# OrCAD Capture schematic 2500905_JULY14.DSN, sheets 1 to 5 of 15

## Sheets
1 PAGE15: size Custom
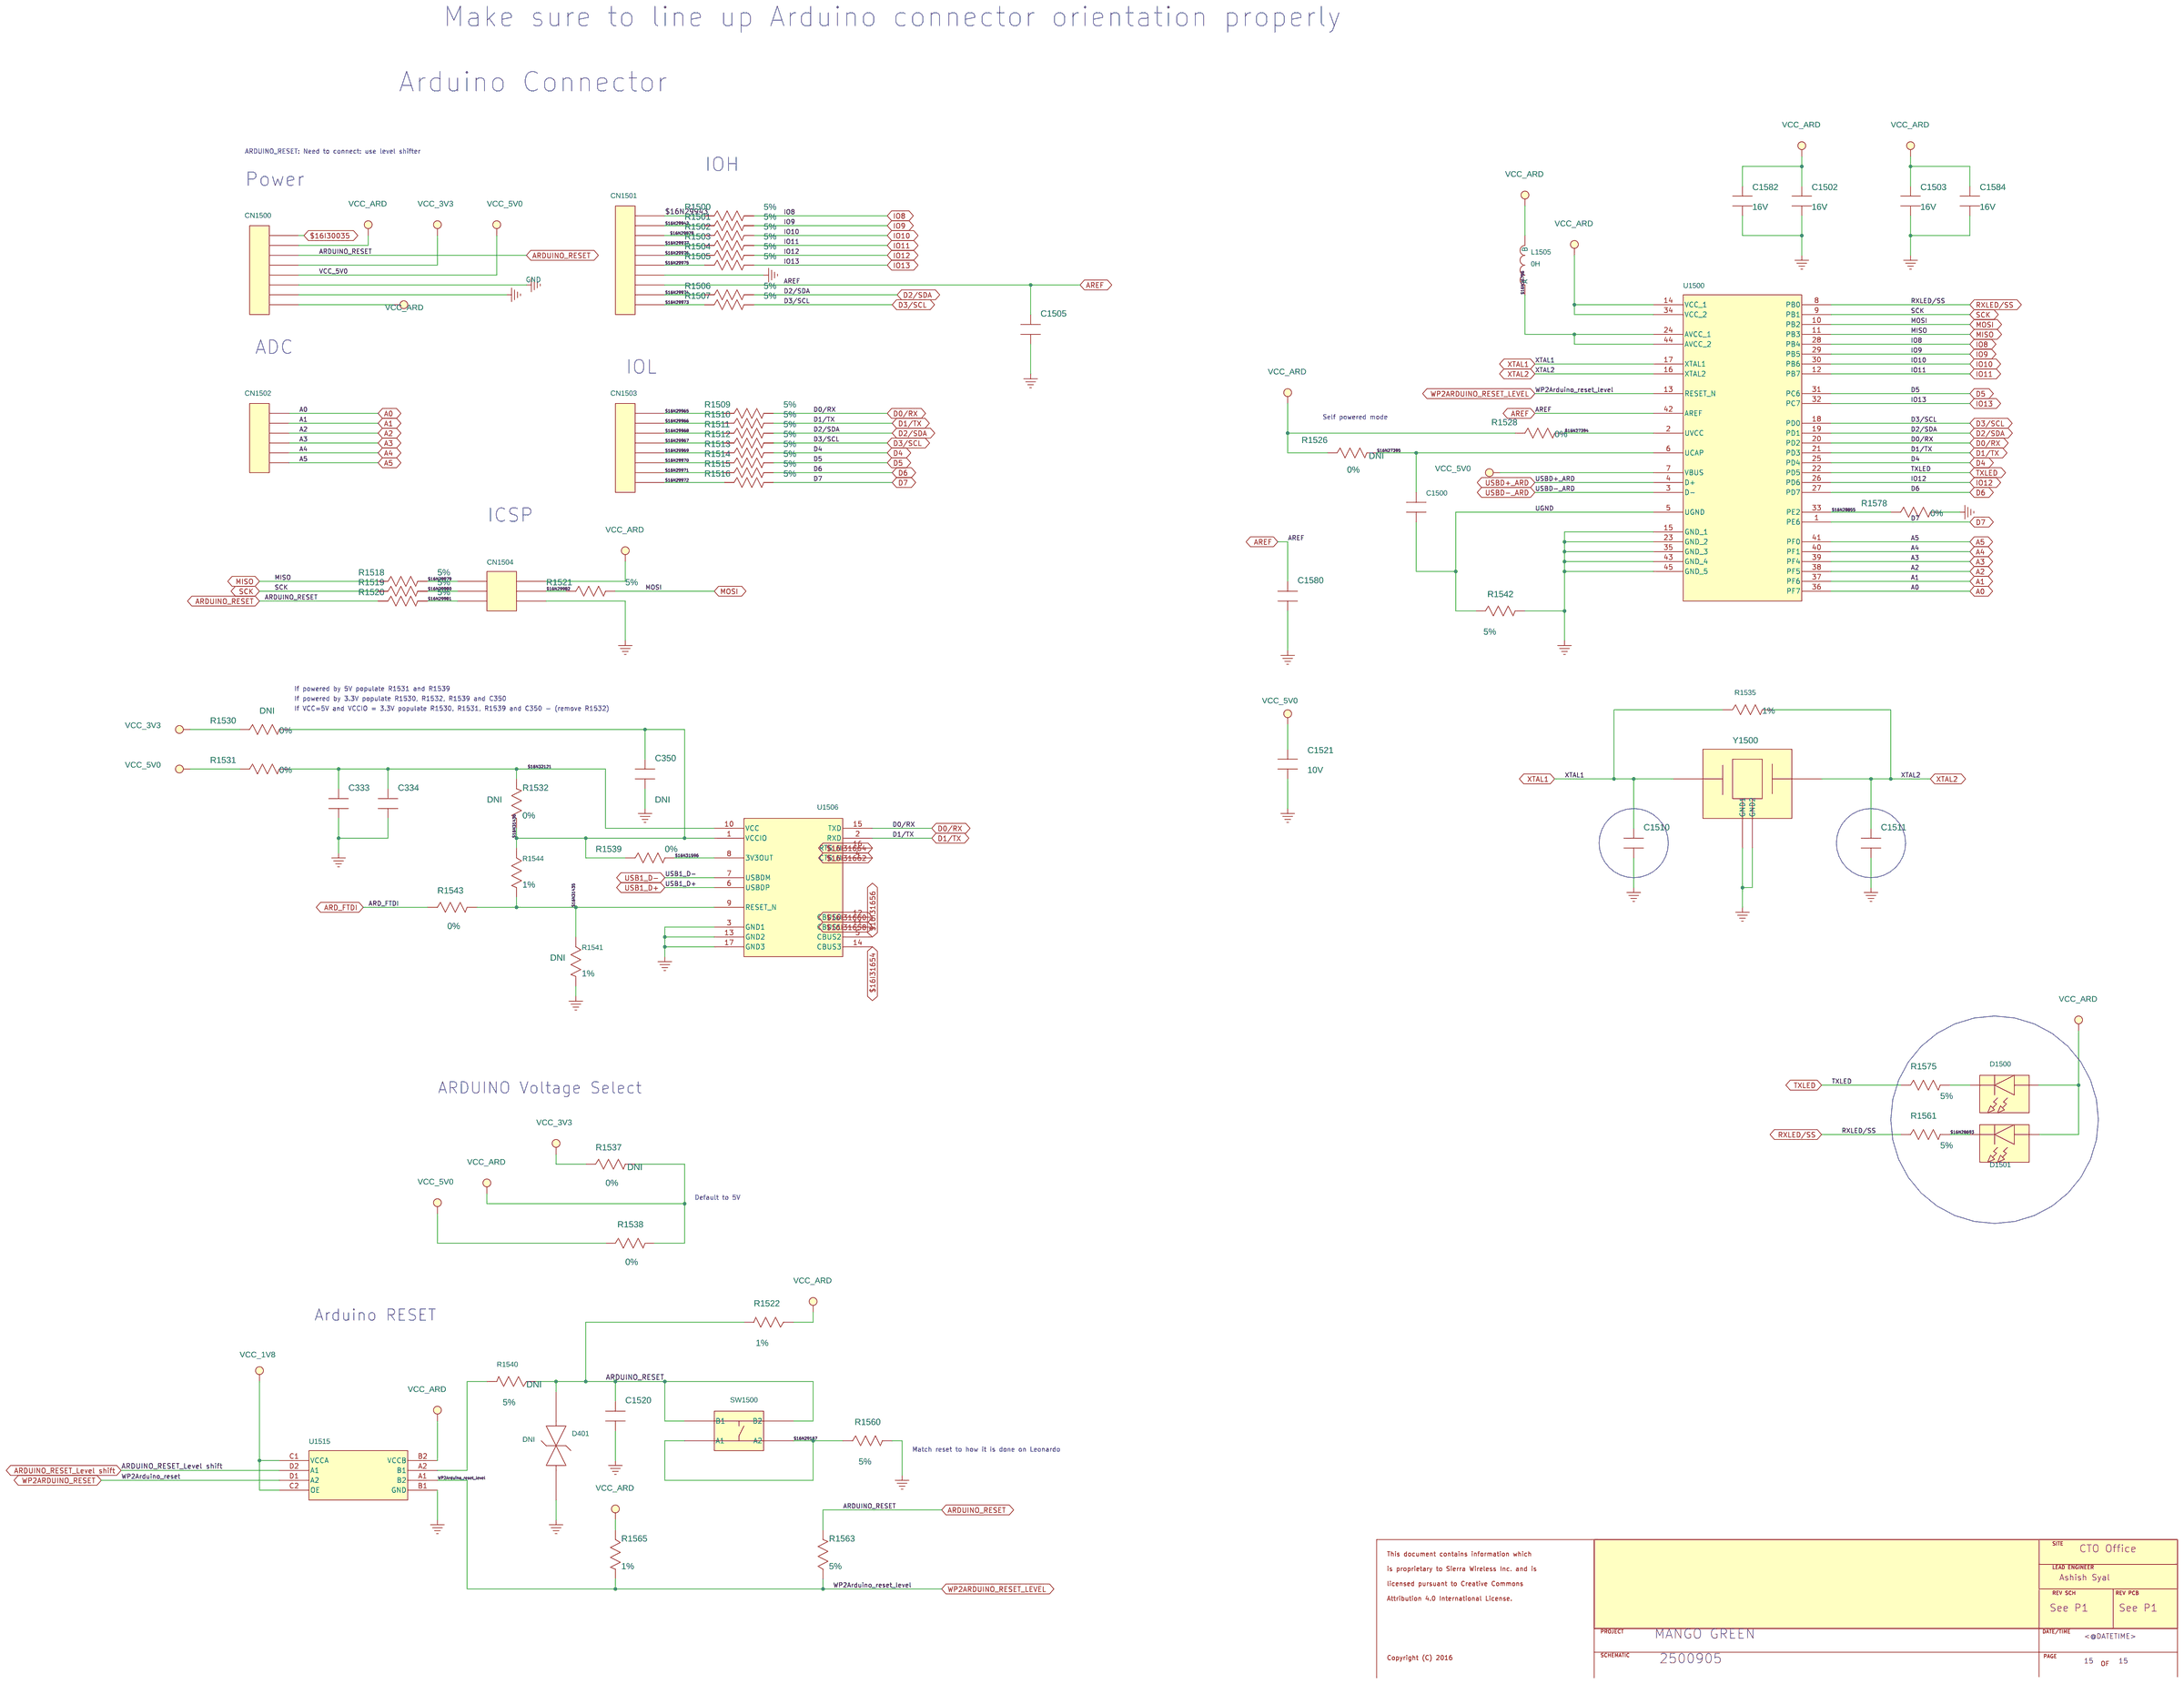
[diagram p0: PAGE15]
2 PAGE14: size Custom
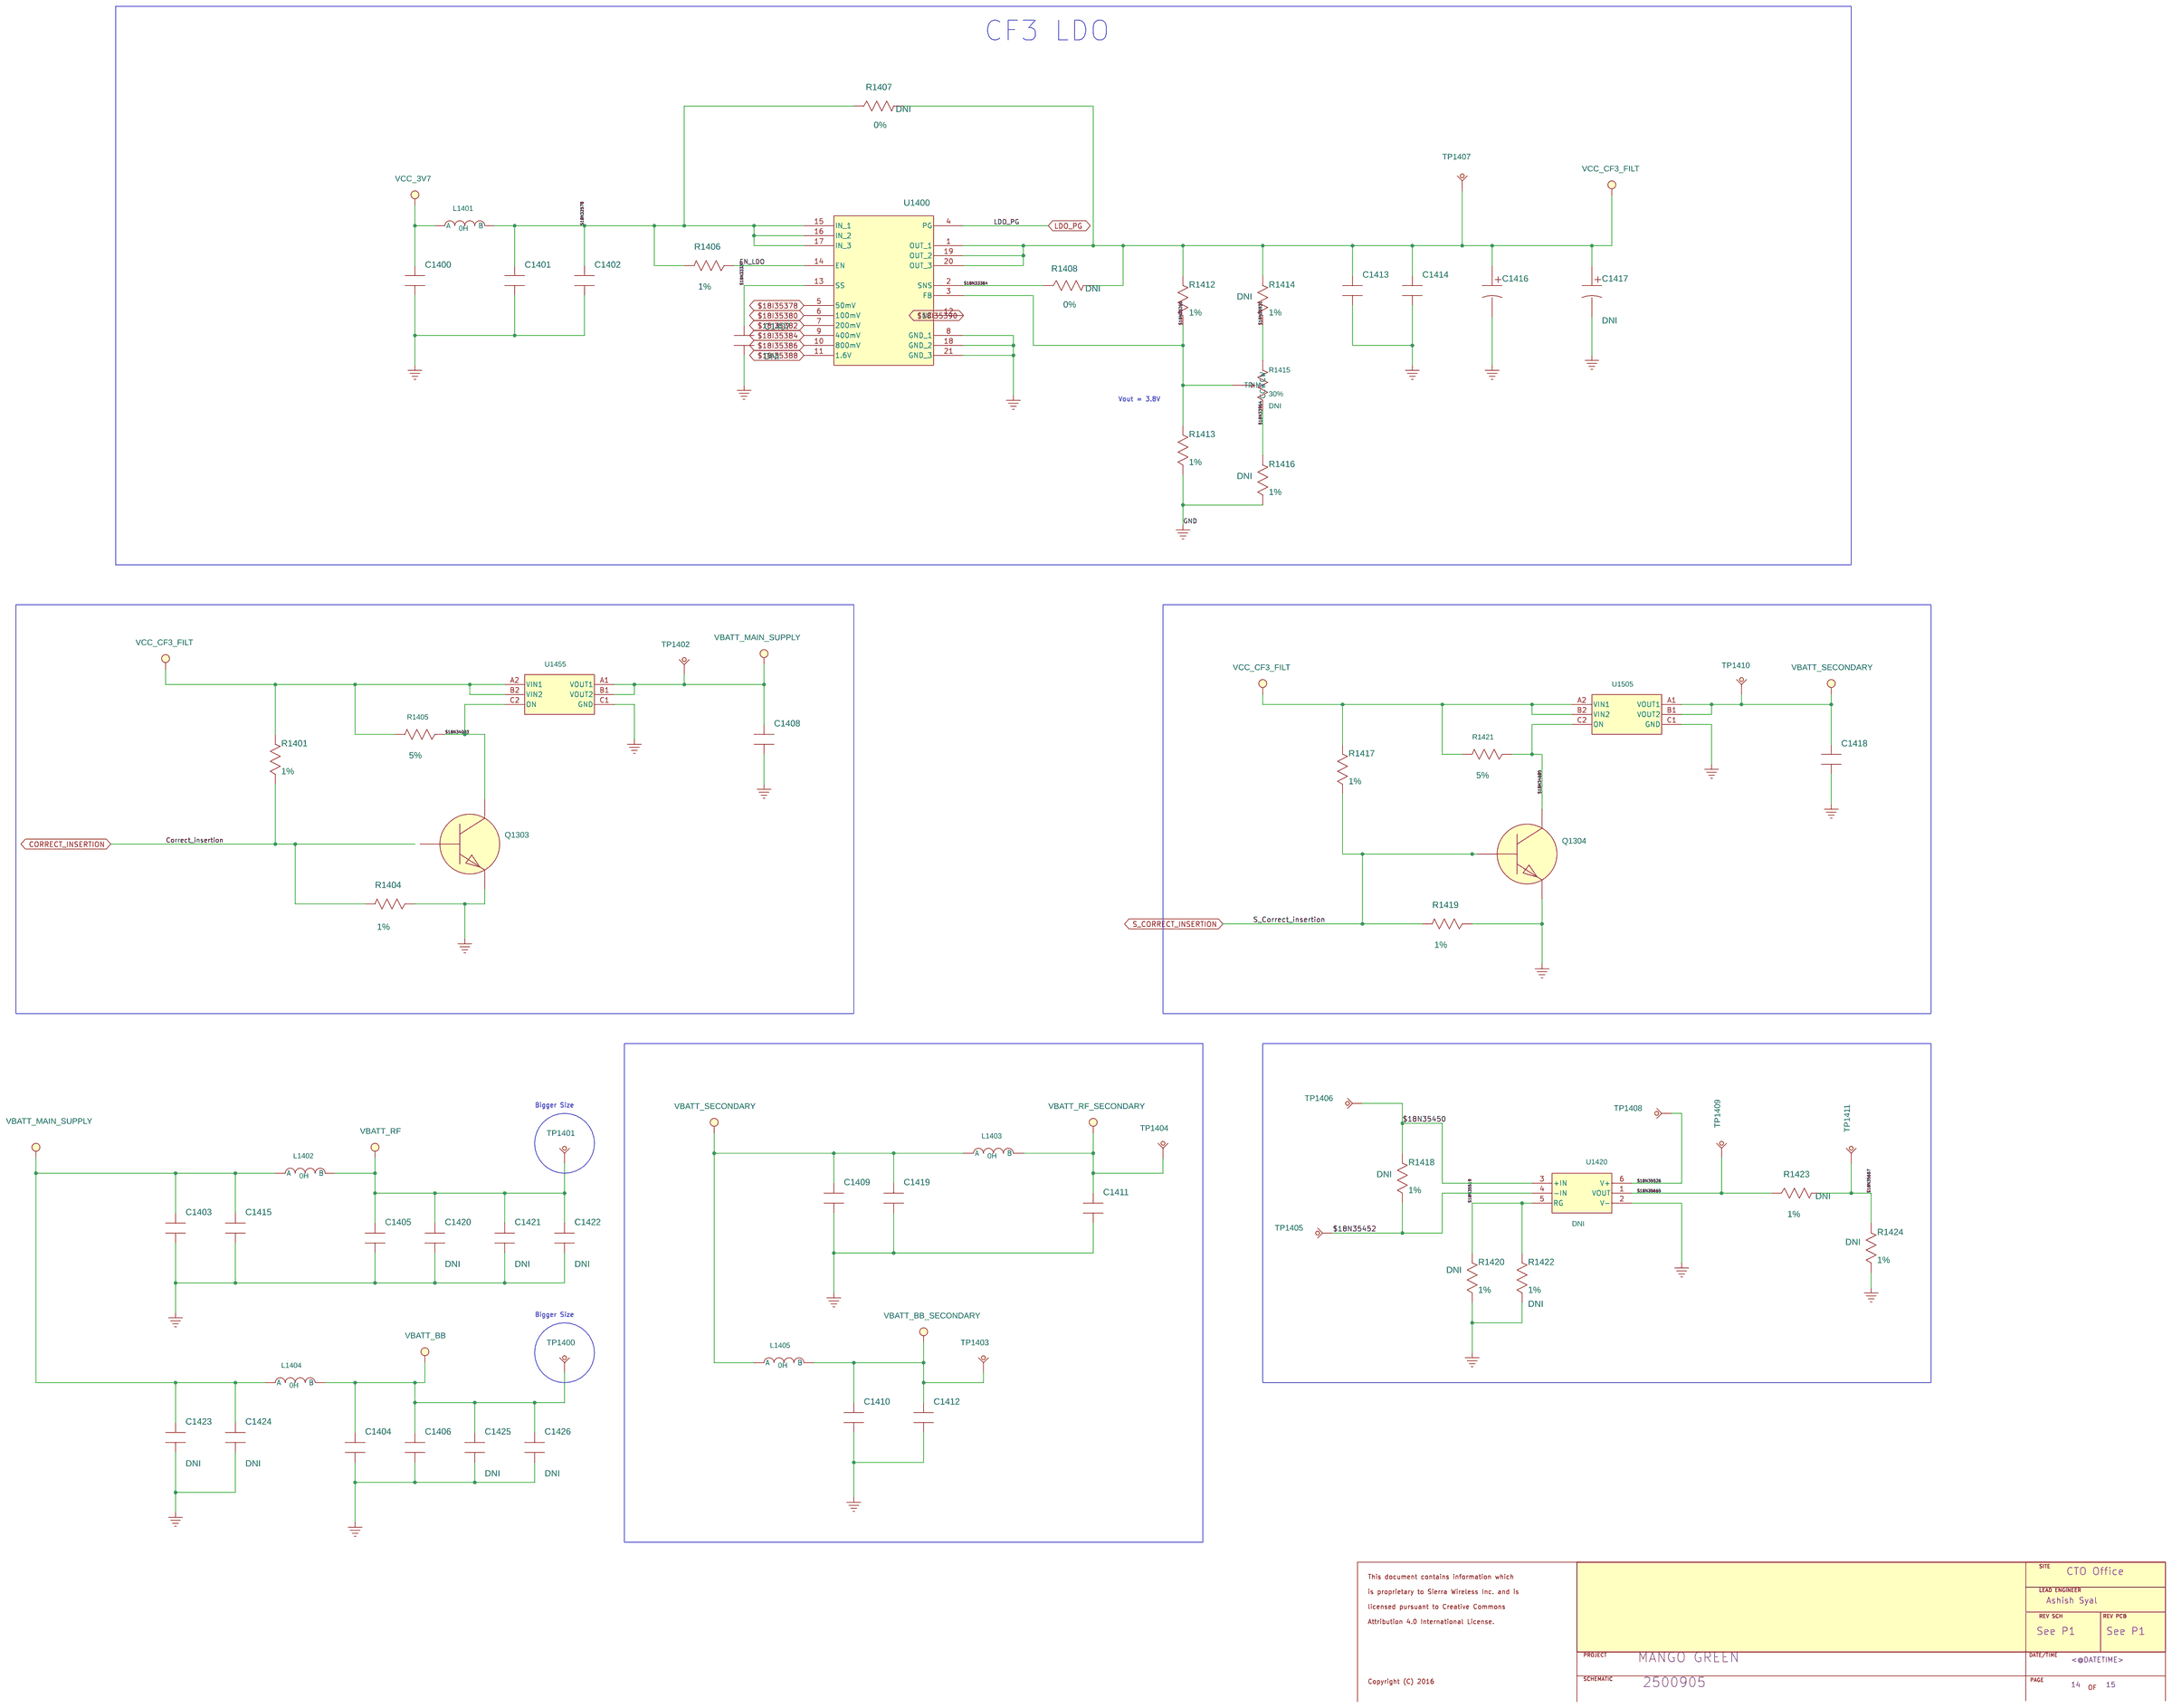
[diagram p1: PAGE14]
3 PAGE13: size Custom
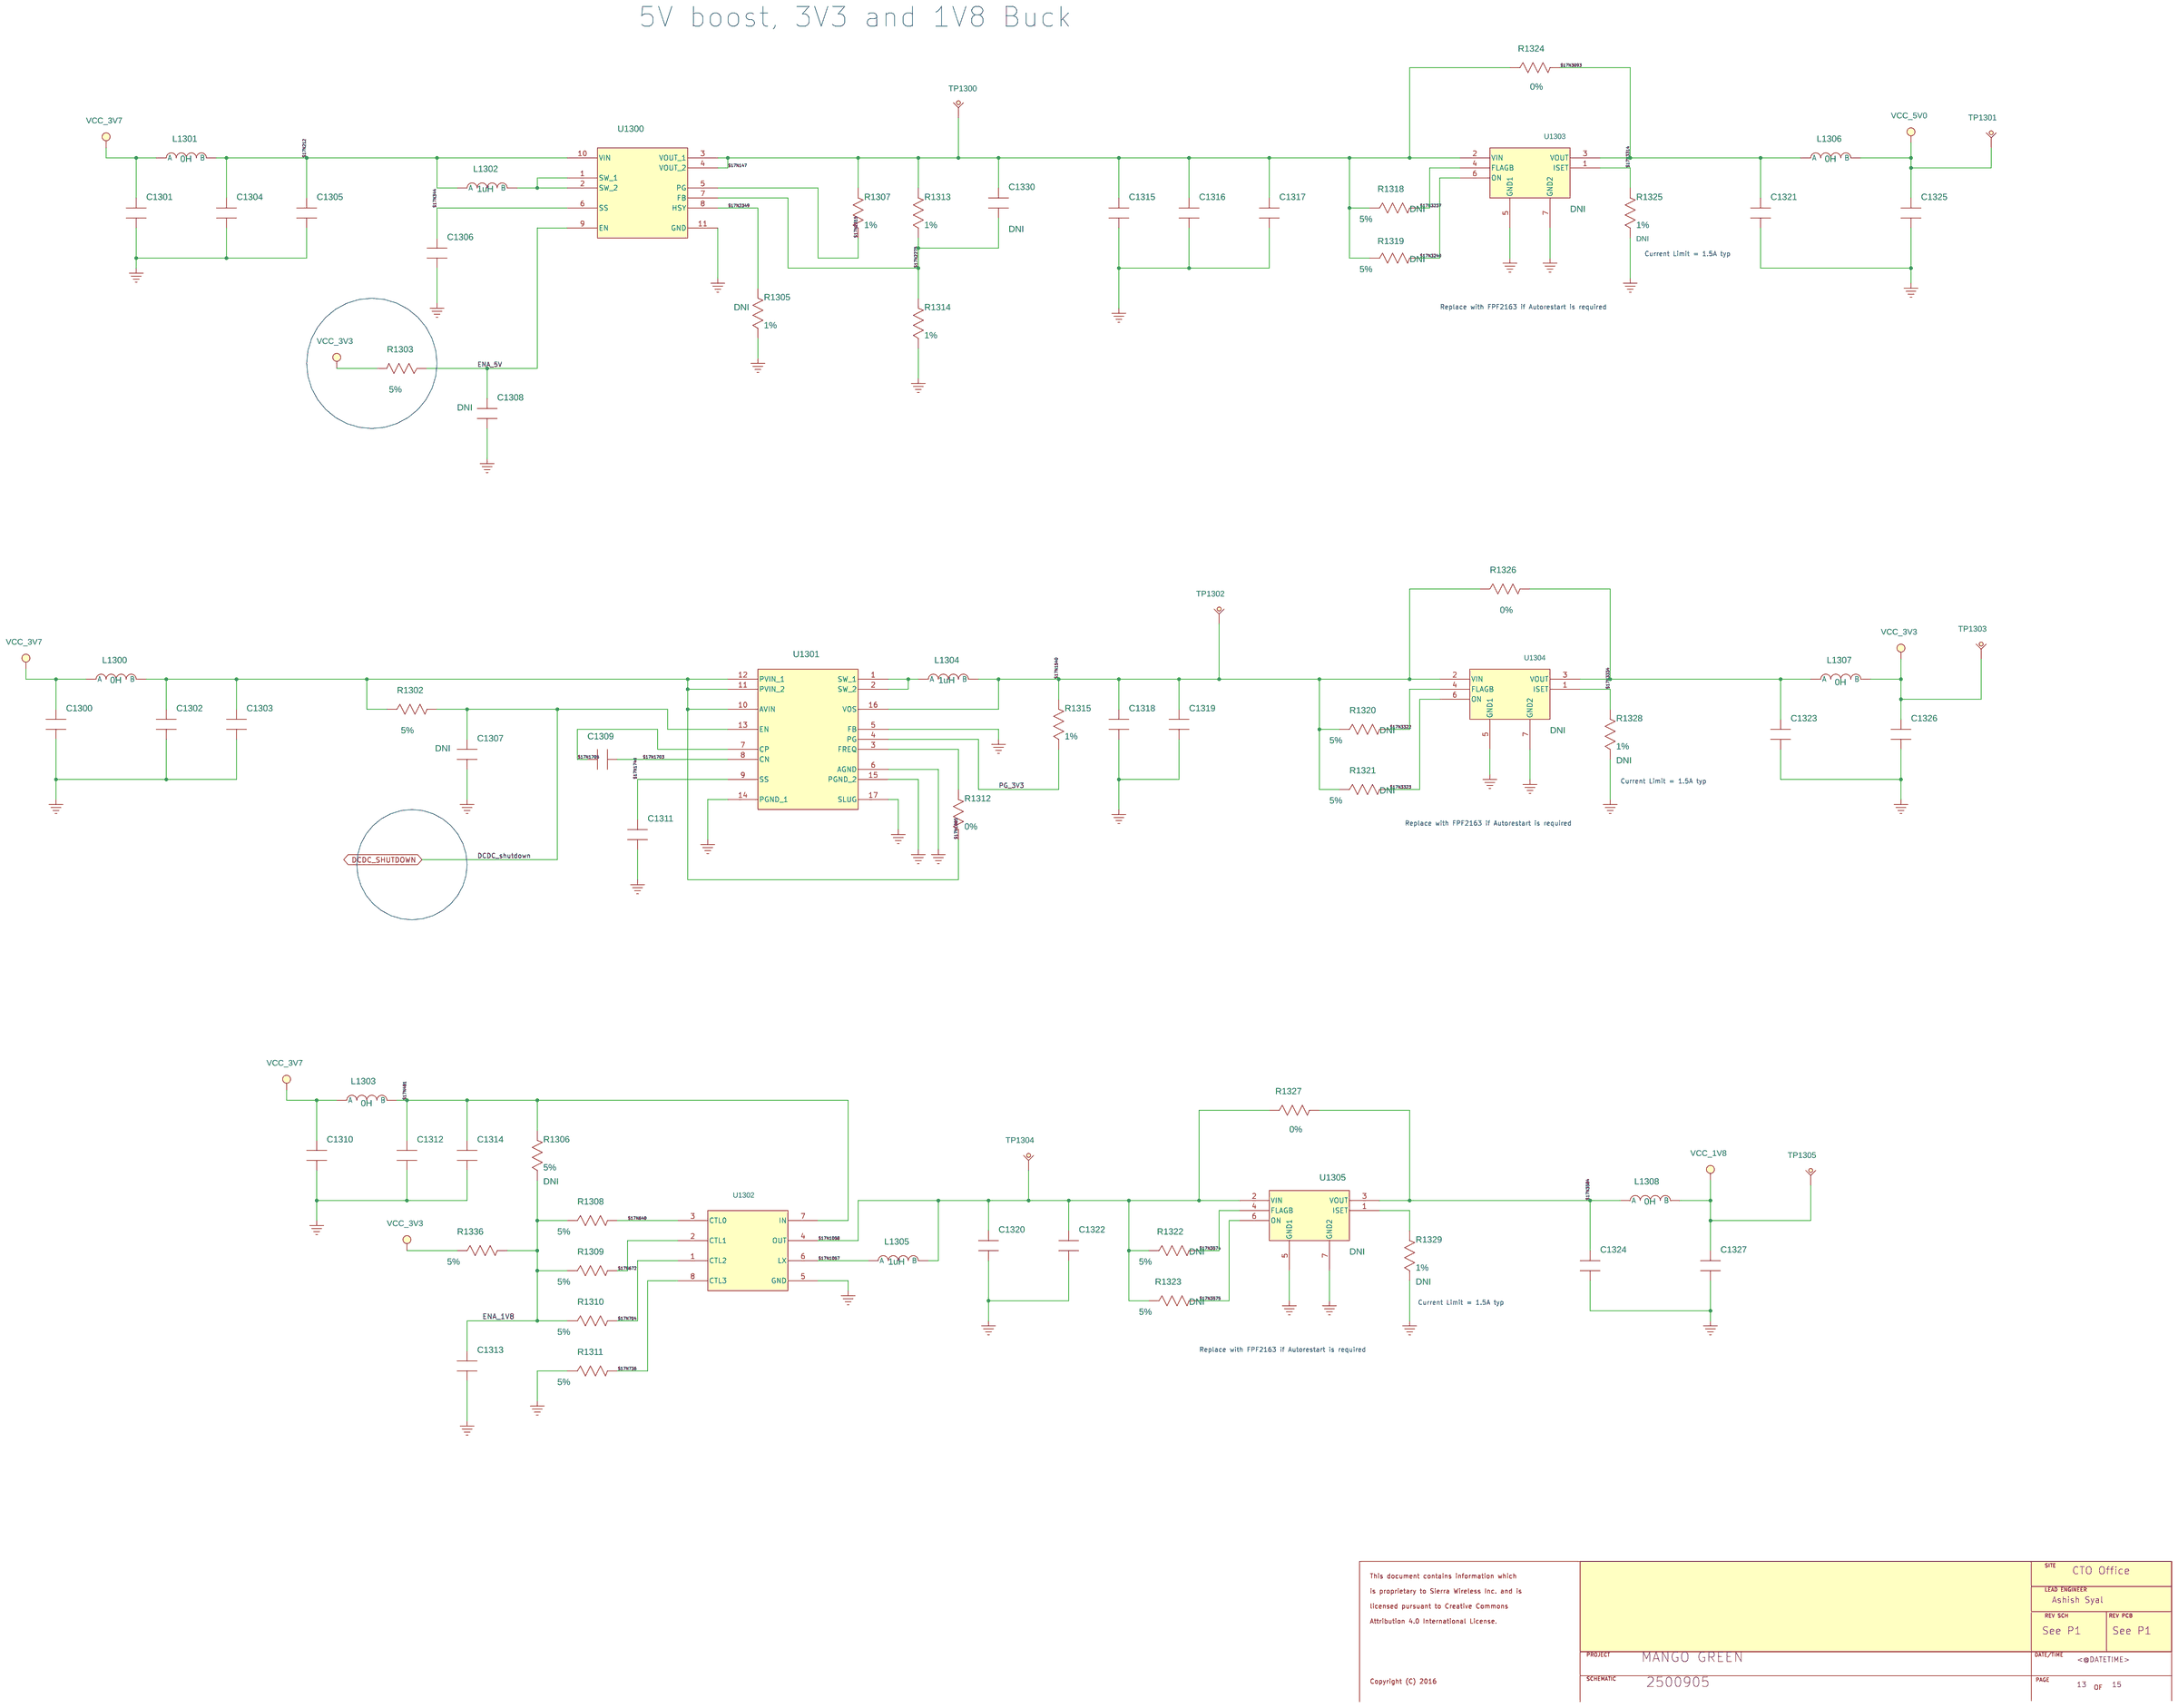
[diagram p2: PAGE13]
4 PAGE12: size Custom
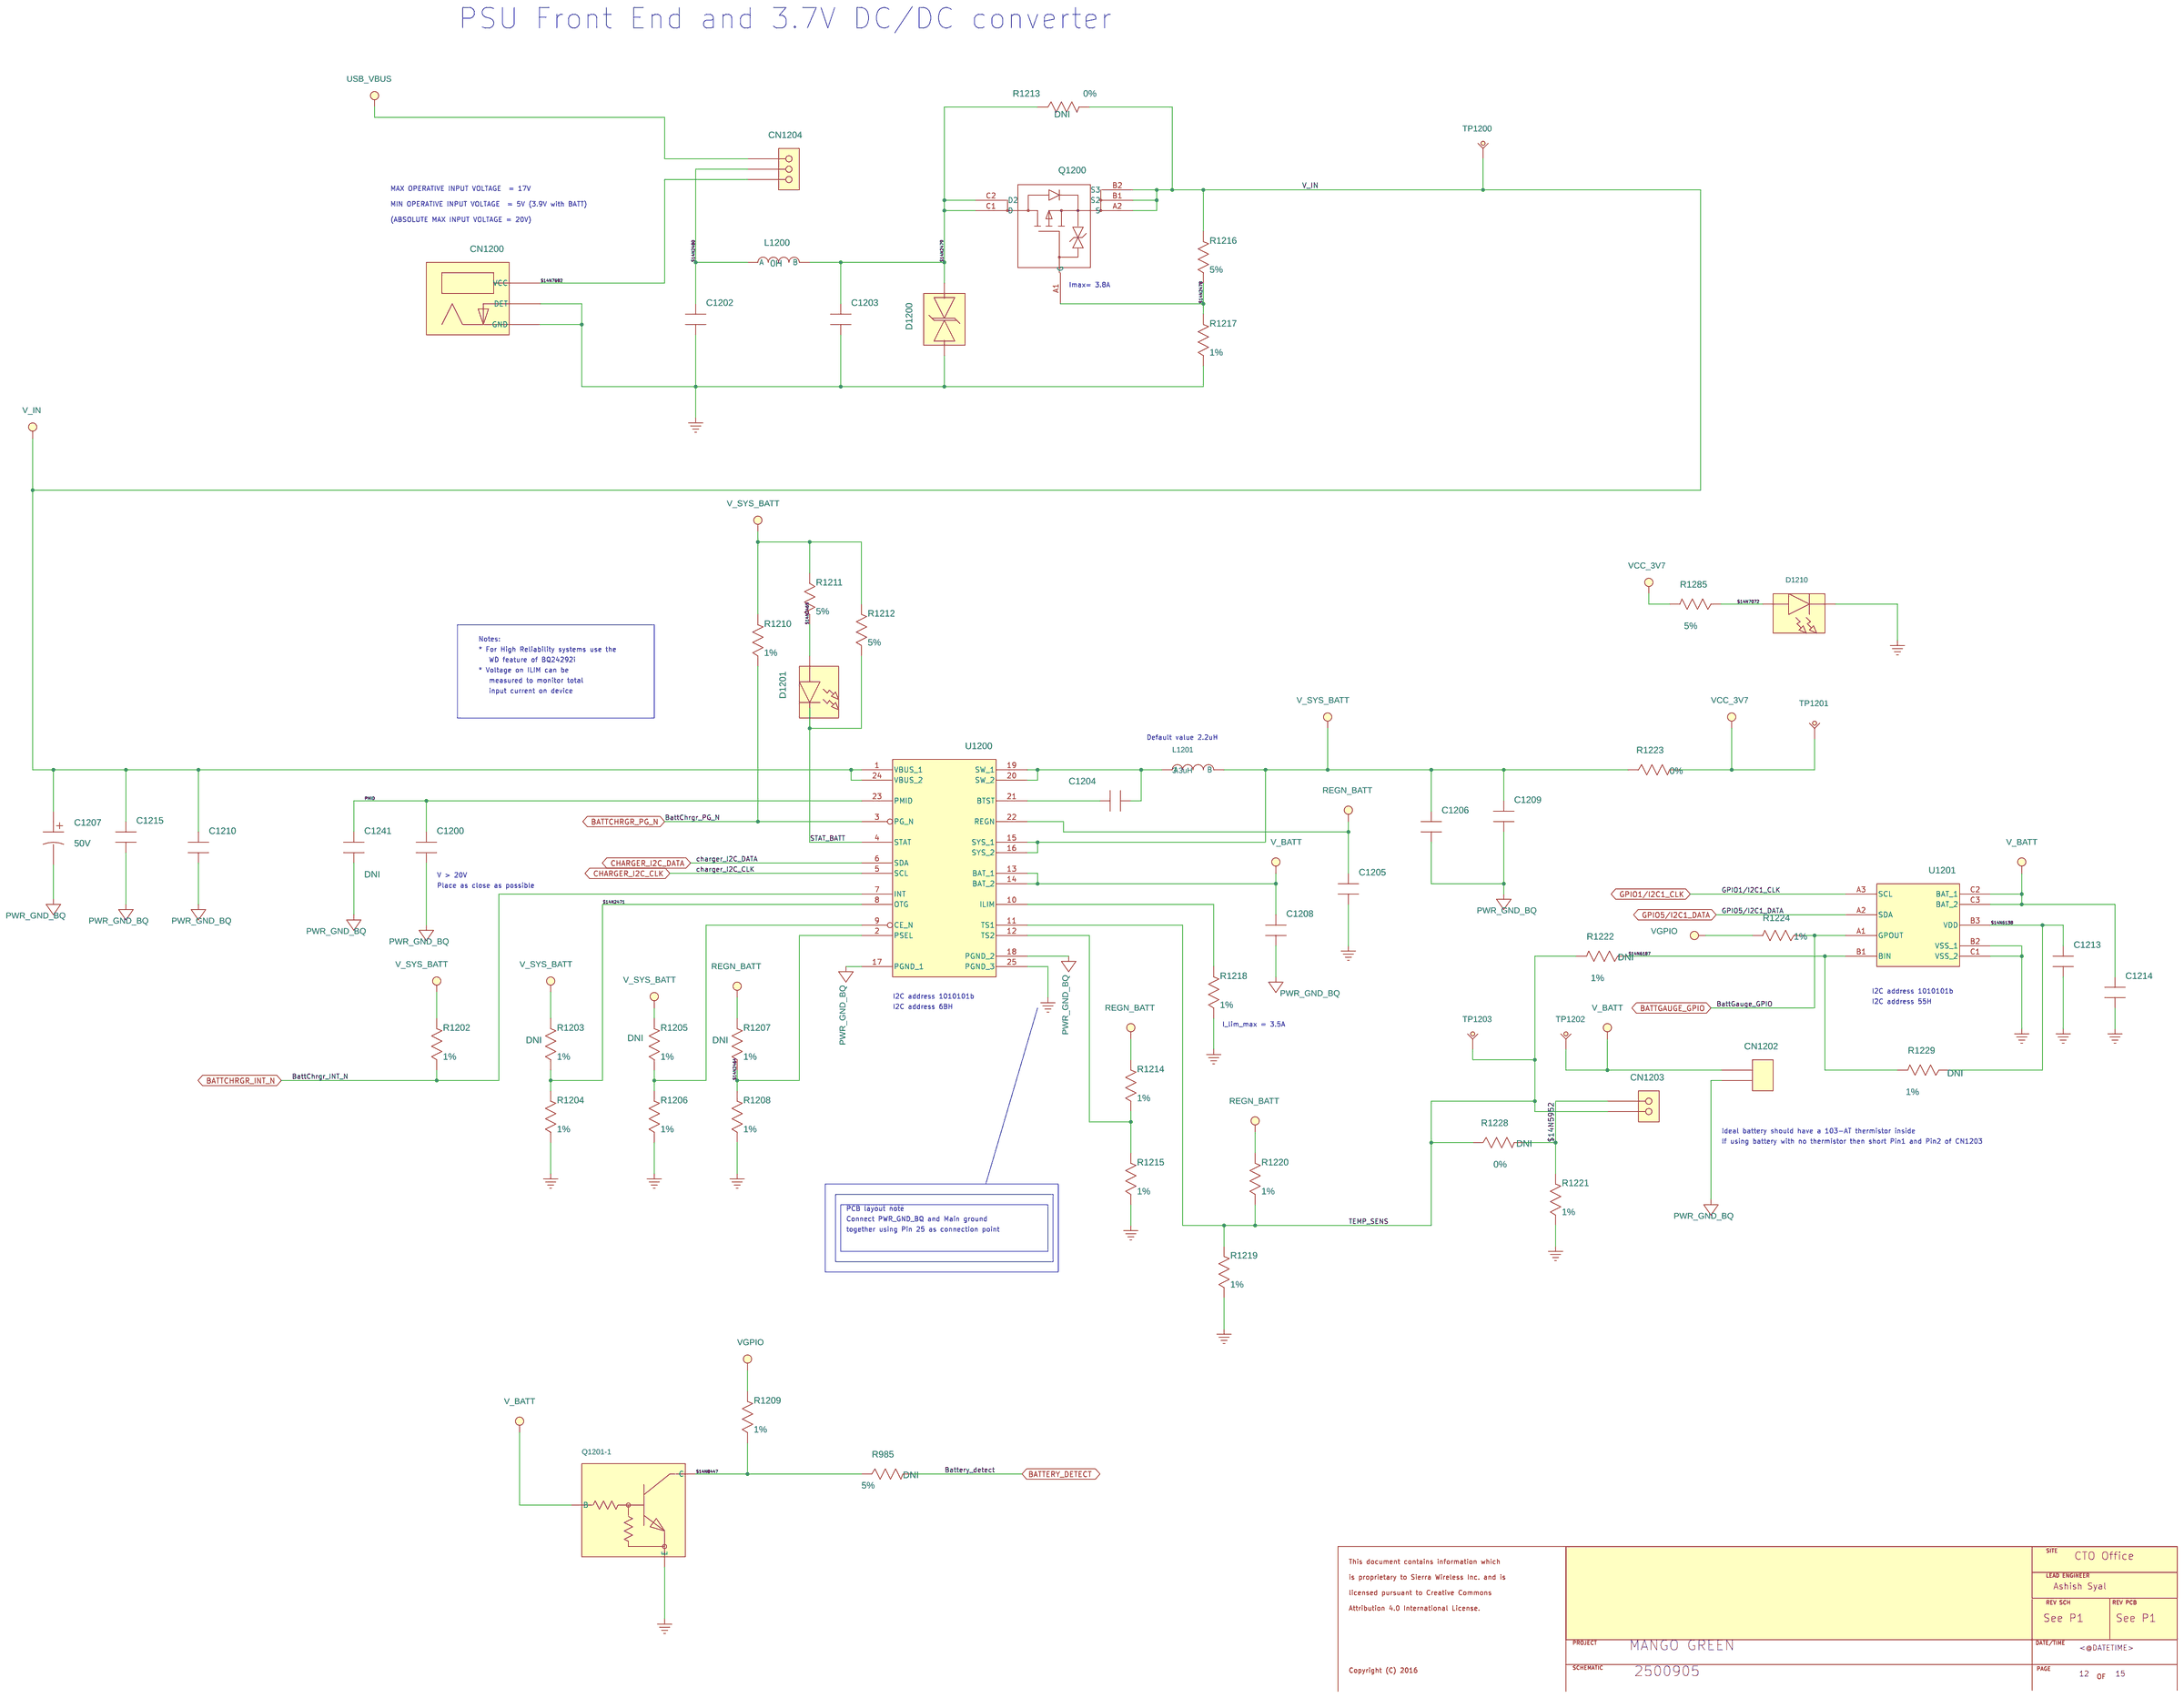
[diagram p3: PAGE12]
5 PAGE11: size Custom
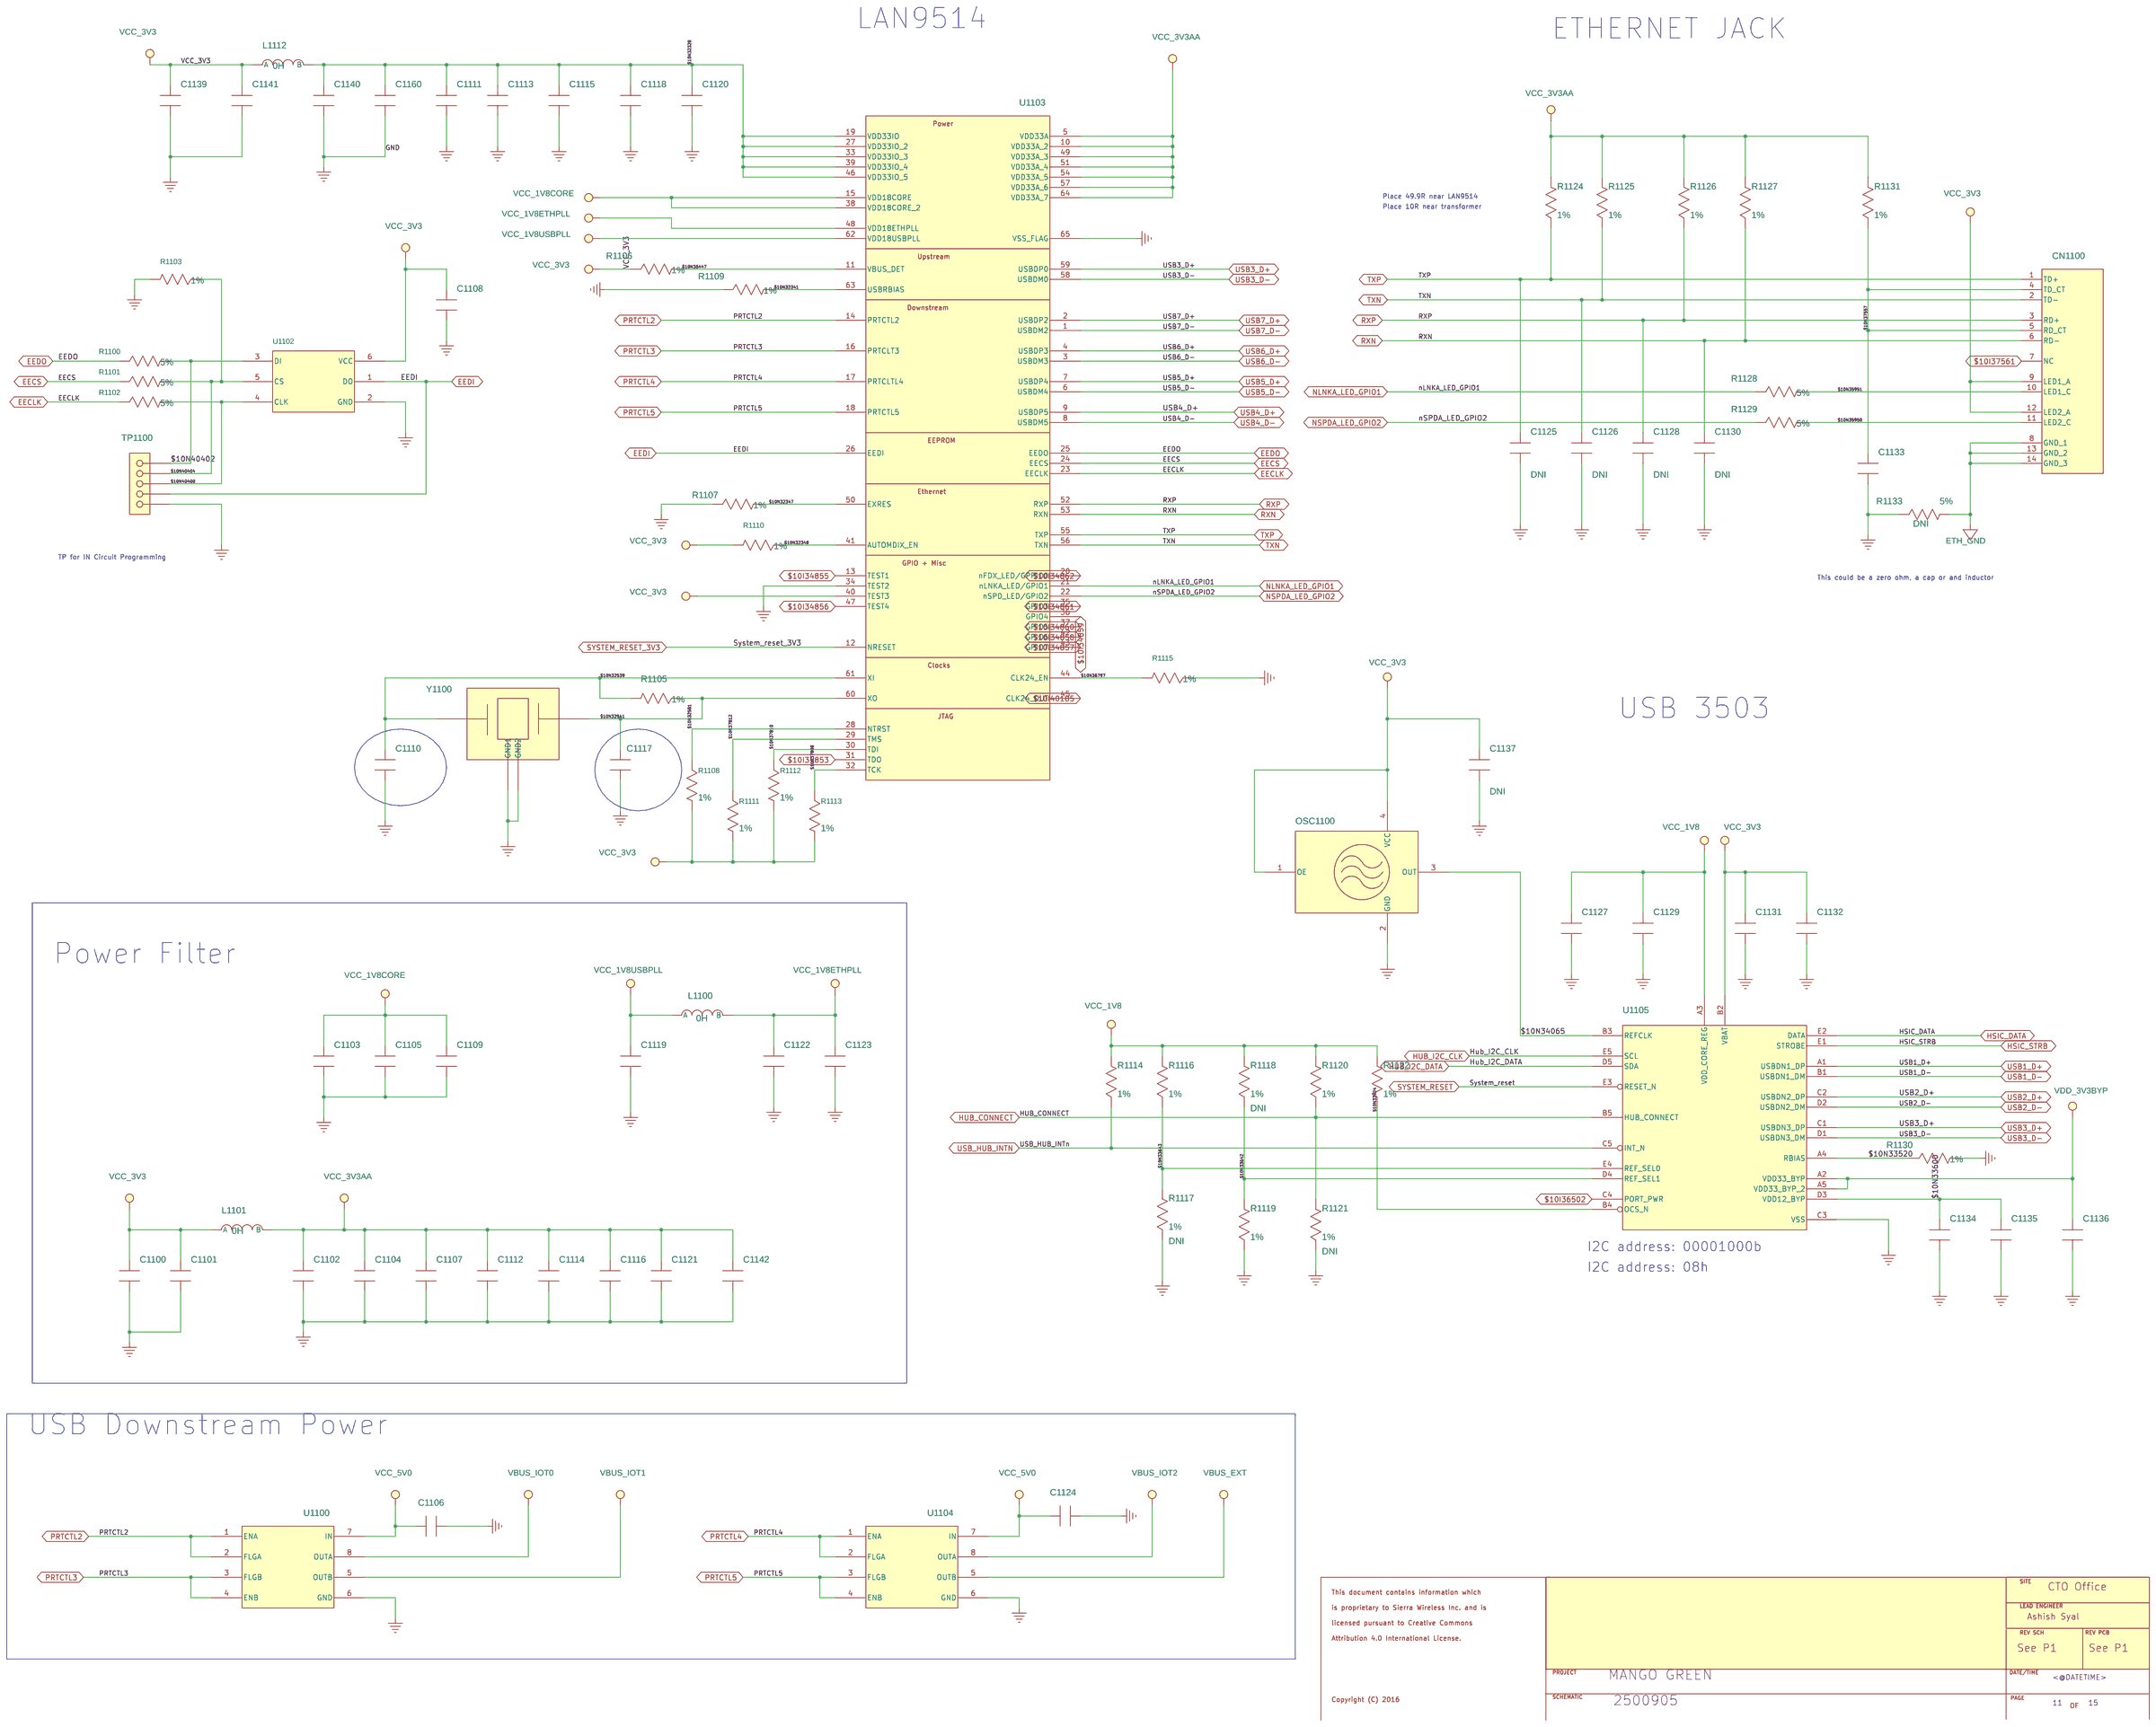
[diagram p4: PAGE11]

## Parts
sheet PAGE11
11  C_OPEN_HW  [TP]
C1100  100nF  [0402C]
C1101  100nF  [0402C]
C1102  100nF  [0402C]
C1103  4.7uF  [0402C]
C1104  100nF  [0402C]
C1105  100nF  [0402C]
C1106  1uF  [0402C]
C1107  100nF  [0402C]
C1108  100nF  [0402C]
C1109  100nF  [0402C]
C1110  22pF  [0402C]
C1111  100nF  [0402C]
C1112  100nF  [0402C]
C1113  100nF  [0402C]
C1114  100nF  [0402C]
C1115  100nF  [0402C]
C1116  100nF  [0402C]
C1117  22pF  [0402C]
C1118  100nF  [0402C]
C1119  4.7uF  [0402C]
C1120  100nF  [0402C]
C1121  4.7uF  [0402C]
C1122  100nF  [0402C]
C1123  4.7uF  [0402C]
C1124  1uF  [0402C]
C1125  15pF  [0402C]
C1126  15pF  [0402C]
C1127  100nF  [0402C]
C1128  15pF  [0402C]
C1129  4.7uF  [0402C]
C1130  15pF  [0402C]
C1131  4.7uF  [0402C]
C1132  100nF  [0402C]
C1133  22nF  [0402C]
C1134  4.7uF  [0402C]
C1135  100nF  [0402C]
C1136  4.7uF  [0402C]
C1137  100nF  [0402C]
C1139  10uF  [0603C]
C1140  10uF  [0603C]
C1141  100nF  [0402C]
C1142  100nF  [0402C]
C1160  100nF  [0402C]
CN1100  J0011D01B  [CONN_12P_1630x2160_0127CC_RJ45_2GND_PULSE]
L1100  0H  [0603L]
L1101  0H  [0603L]
L1112  0H  [0603L]
OSC1100  26MEGHz  [XTAL_4P_AP3S]
R1100  620  [0402R]
R1101  620  [0402R]
R1102  620  [0402R]
R1103  10K  [0402R]
R1105  1MEG  [0402R]
R1106  825  [0402R]
R1107  12.4K  [0402R]
R1108  10K  [0402R]
R1109  12K  [0402R]
R1110  10K  [0402R]
R1111  10K  [0402R]
R1112  10K  [0402R]
R1113  10K  [0402R]
R1114  10K  [0402R]
R1115  10K  [0402R]
R1116  10K  [0402R]
R1117  10K  [0402R]
R1118  10K  [0402R]
R1119  10K  [0402R]
R1120  10K  [0402R]
R1121  10K  [0402R]
R1122  10K  [0402R]
R1124  49.9  [0805R]
R1125  49.9  [0805R]
R1126  49.9  [0805R]
R1127  49.9  [0805R]
R1128  330  [0402R]
R1129  330  [0402R]
R1130  12K  [0402R]
R1131  10  [0402R]
R1133  20m  [1206R]
TP1100  TESTPOINT_5P_0100_RND_0127CC  [TP_5P_0100_RND_0127CC]
U1100  IC2026  [SOIC_8P_0490x0390_0127CC]
U1102  2Kbit SERIAL EEPROM  [SOT23_6P_0300x0160_0095CC]
U1103  LAN9514-JZX  [QFN_64P_0900x0900_SLUG_0730x0730_0050CC]
U1104  IC2026  [SOIC_8P_0490x0390_0127CC]
U1105  USB3503A  [BGA_25P_0200x0200_0040CC_0030PD]
Y1100  25MEGHz  [XTAL_4P_0200X0160]
sheet PAGE12
12  C_OPEN_HW  [TP]
C1200  10uF  [1206C]
C1202  220nF  [0603C]
C1203  220nF  [0603C]
C1204  47nF  [0402C]
C1205  4.7uF  [0603C]
C1206  100nF  [0402C]
C1207  22uF  [CAP_2P_0660x0660_POL]
C1208  10uF  [0603C]
C1209  47uF  [1206C]
C1210  1uF  [0603C]
C1213  470nF  [0402C]
C1214  1uF  [0402C]
C1215  220nF  [0603C]
C1241  1uF  [0603C]
CN1200  FC681465P  [CONN_3P_1450x0900_DC_PWR_JACK_CLIFF]
CN1202  B2B-PH-K-S  [CONN_2P_0590x0450_0200CC_THRU_HEADER]
CN1203  POST TERMINAL STRIP  [CONN_2P_0508x0254_VERTICAL_HEADER_SINGLE_ROW_THRU_SAMTEC_TSW]
CN1204  POST TERMINAL STRIP  [CONN_3P_0762x0254_VERTICAL_HEADER_SINGLE_ROW_THRU_SAMTEC_TSW]
D1200  SMAJ20CA  [DIO_2P_0435x0260_SMA]
D1201  LED  [0603D]
D1210  LED  [0603D]
L1200  0H  [1812L]
L1201  3.3uH  [IND_2P_0400X0400_0237CC_COILCRAFT]
Q1200  MOSFET P-CHANNEL  [BGA_6P_0100x0150_0050CC_0030PD]
Q1201  NPN  [SOT963_6P_0100x0080_0035CC]  (section -1)
R985  33  [0402R]
R1202  10K  [0402R]
R1203  10K  [0402R]
R1204  10K  [0402R]
R1205  10K  [0402R]
R1206  10K  [0402R]
R1207  10K  [0402R]
R1208  10K  [0402R]
R1209  10K  [0402R]
R1210  10K  [0402R]
R1211  300  [0402R]
R1212  47K  [0402R]
R1213  0  [0603R]
R1214  10K  [0402R]
R1215  15K  [0402R]
R1216  100K  [0603R]
R1217  10K  [0402R]
R1218  150  [0402R]
R1219  30.1K  [0402R]
R1220  5.23K  [0402R]
R1221  10K  [0402R]
R1222  10K  [0402R]
R1223  0  [0603R]
R1224  10K  [0402R]
R1228  0  [0402R]
R1229  1MEG  [0402R]
R1285  300  [0402R]
TP1200  TESTPOINT_0100_RND  [TP_0100_RND_NP]
TP1201  TESTPOINT_0100_RND  [TP_0100_RND_NP]
TP1202  TESTPOINT_0100_RND  [TP_0100_RND_NP]
TP1203  TESTPOINT_0100_RND  [TP_0100_RND_NP]
U1200  BQ24192IRGER  [QFN_24P_0400x0400_SLUG_0270x0270_0050CC]
U1201  BQ27621YZFR-G1A  [BGA_9P_0162x0158_0050CC_0030PD]
sheet PAGE13
13  C_OPEN_HW  [TP]
C1300  100nF  [0402C]
C1301  100nF  [0402C]
C1302  100nF  [0402C]
C1303  47uF  [1206C]
C1304  100nF  [0402C]
C1305  47uF  [1206C]
C1306  10nF  [0402C]
C1307  10nF  [0402C]
C1308  10nF  [0402C]
C1309  10nF  [0402C]
C1310  100nF  [0402C]
C1311  10nF  [0402C]
C1312  100nF  [0402C]
C1313  100nF  [0402C]
C1314  47uF  [1206C]
C1315  47uF  [1206C]
C1316  47uF  [1206C]
C1317  100nF  [0402C]
C1318  47uF  [1206C]
C1319  100nF  [0402C]
C1320  10uF  [0402C]
C1321  100nF  [0402C]
C1322  100nF  [0402C]
C1323  100nF  [0402C]
C1324  100nF  [0402C]
C1325  100nF  [0402C]
C1326  100nF  [0402C]
C1327  100nF  [0402C]
C1330  100nF  [0402C]
L1300  0H  [0603L]
L1301  0H  [0603L]
L1302  1uH  [IND_2P_0400x0400_0320CC_TOKO]
L1303  0H  [0603L]
L1304  1uH  [IND_2P_0400x0400_0320CC_TOKO]
L1305  1uH  [0805L]
L1306  0H  [0603L]
L1307  0H  [0603L]
L1308  0H  [0603L]
R1302  51K  [0402R]
R1303  51K  [0402R]
R1305  1MEG  [0402R]
R1306  10K  [0402R]
R1307  1MEG  [0402R]
R1308  10K  [0402R]
R1309  10K  [0402R]
R1310  10K  [0402R]
R1311  10K  [0402R]
R1312  0  [0402R]
R1313  365K  [0402R]
R1314  91K  [0402R]
R1315  499K  [0402R]
R1318  51K  [0402R]
R1319  51K  [0402R]
R1320  51K  [0402R]
R1321  51K  [0402R]
R1322  51K  [0402R]
R1323  51K  [0402R]
R1324  0  [0603R]
R1325  182  [0402R]
R1326  0  [0603R]
R1327  0  [0603R]
R1328  182  [0402R]
R1329  182  [0402R]
R1336  51K  [0402R]
TP1300  TESTPOINT_0100_RND  [TP_0100_RND_NP]
TP1301  TESTPOINT_0100_RND  [TP_0100_RND_NP]
TP1302  TESTPOINT_0100_RND  [TP_0100_RND_NP]
TP1303  TESTPOINT_0100_RND  [TP_0100_RND_NP]
TP1304  TESTPOINT_0100_RND  [TP_0100_RND_NP]
TP1305  TESTPOINT_0100_RND  [TP_0100_RND_NP]
U1300  TPS61230DRCR  [DFN_10P_0300x0300_SLUG_0240x0165_0050CC]
U1301  TPS62091RGTR  [QFN_16P_0300x0300_SLUG_0170x0170_0050CC]
U1302  SC195ULTRT  [QFN_8P_0150x0150_0040CC]
U1303  FPF2164  [DFN_6P_0200x0200_SLUG_0140x0080_0065CC]
U1304  FPF2164  [DFN_6P_0200x0200_SLUG_0140x0080_0065CC]
U1305  FPF2164  [DFN_6P_0200x0200_SLUG_0140x0080_0065CC]
sheet PAGE14
14  C_OPEN_HW  [TP]
C1400  100nF  [0402C]
C1401  100nF  [0402C]
C1402  10uF  [0603C]
C1403  47uF  [1206C]
C1404  47uF  [1206C]
C1405  100nF  [0402C]
C1406  100nF  [0402C]
C1407  47nF  [0402C]
C1408  100nF  [0402C]
C1409  47uF  [1206C]
C1410  47uF  [1206C]
C1411  100nF  [0402C]
C1412  100nF  [0402C]
C1413  47uF  [1206C]
C1414  100nF  [0402C]
C1415  100nF  [0402C]
C1416  1.5mF  [CAP_2P_0720x0630_POL_NIB]
C1417  1.5mF  [CAP_2P_0720x0630_POL_NIB]
C1418  100nF  [0402C]
C1419  100nF  [0402C]
C1420  100nF  [0402C]
C1421  100nF  [0402C]
C1422  100nF  [0402C]
C1423  100nF  [0402C]
C1424  100nF  [0402C]
C1425  100nF  [0402C]
C1426  100nF  [0402C]
L1401  0H  [0603L]
L1402  0H  [0603L]
L1403  0H  [0603L]
L1404  0H  [0603L]
L1405  0H  [0603L]
Q1303  NPN  [SOT723_3P_0120x0080_0080CC]
Q1304  NPN  [SOT723_3P_0120x0080_0080CC]
R1401  1.5K  [0402R]
R1404  220K  [0402R]
R1405  51K  [0402R]
R1406  33K  [0402R]
R1407  0  [0402R]
R1408  0  [0402R]
R1412  220K  [0402R]
R1413  33K  [0402R]
R1414  33K  [0402R]
R1415  100K  [POT_3P_0310x0360_0175CC_VERTICAL_MURATA_PVZ3A]
R1416  33K  [0402R]
R1417  1.5K  [0402R]
R1418  100m  [2010R]
R1419  220K  [0402R]
R1420  100K  [0402R]
R1421  51K  [0402R]
R1422  100K  [0402R]
R1423  10K  [0402R]
R1424  10K  [0402R]
TP1400  TESTPOINT_0200_RND  [TP_0200_RND_NP]
TP1401  TESTPOINT_0200_RND  [TP_0200_RND_NP]
TP1402  TESTPOINT_0100_RND  [TP_0100_RND_NP]
TP1403  TESTPOINT_0100_RND  [TP_0100_RND_NP]
TP1404  TESTPOINT_0100_RND  [TP_0100_RND_NP]
TP1405  TESTPOINT_0100_RND  [TP_0100_RND_NP]
TP1406  TESTPOINT_0100_RND  [TP_0100_RND_NP]
TP1407  TESTPOINT_0100_RND  [TP_0100_RND_NP]
TP1408  TESTPOINT_0100_RND  [TP_0100_RND_NP]
TP1409  TESTPOINT_0100_RND  [TP_0100_RND_NP]
TP1410  TESTPOINT_0100_RND  [TP_0100_RND_NP]
TP1411  TESTPOINT_0100_RND  [TP_0100_RND_NP]
U1400  TPS7A7300  [QFN_20P_0500x0500_SLUG_0320x0320_0065CC]
U1420  LMP8645  [SOT23_6P_0300x0160_0095CC]
U1455  TPS22964CYZPR  [BGA_6P_0100x0150_0050CC_0030PD]
U1505  TPS22964CYZPR  [BGA_6P_0100x0150_0050CC_0030PD]
sheet PAGE15
15  C_OPEN_HW  [TP]
C333  100nF  [0402C]
C334  4.7uF  [0402C]
C350  100nF  [0402C]
C1500  1uF  [0402C]
C1502  1uF  [0402C]
C1503  1uF  [0402C]
C1505  1nF  [0402C]
C1510  22pF  [0402C]
C1511  22pF  [0402C]
C1520  100nF  [0402C]
C1521  10uF  [0805C]
C1580  100nF  [0402C]
C1582  1uF  [0402C]
C1584  1uF  [0402C]
CN1500  SSW-108-01-F-S  [CONN_8P_2050x0241_0254CC_THRU]
CN1501  SSW-110-01-F-S  [CONN_10P_2550x0241_0254CC_THRU]
CN1502  SSW-106-01-F-S  [CONN_6P_1550x0241_0254CC_THRU]
CN1503  SSW-108-01-F-S  [CONN_8P_2050x0241_0254CC_THRU]
CN1504  TSW-103-07-G-D  [CONN_6P_0760x0510_HEADER_THRU_0254CC]
D401  0.05pF  [0402E]
D1500  LED  [0603D]
D1501  LED  [0603D]
L1505  0H  [0603L]
R1500  33  [0402R]
R1501  33  [0402R]
R1502  33  [0402R]
R1503  33  [0402R]
R1504  33  [0402R]
R1505  33  [0402R]
R1506  33  [0402R]
R1507  33  [0402R]
R1509  33  [0402R]
R1510  33  [0402R]
R1511  33  [0402R]
R1512  33  [0402R]
R1513  33  [0402R]
R1514  33  [0402R]
R1515  33  [0402R]
R1516  33  [0402R]
R1518  33  [0402R]
R1519  33  [0402R]
R1520  33  [0402R]
R1521  33  [0402R]
R1522  10K  [0402R]
R1526  0  [0402R]
R1528  0  [0402R]
R1530  0  [0402R]
R1531  0  [0402R]
R1532  0  [0402R]
R1535  1MEG  [0402R]
R1537  0  [0603R]
R1538  0  [0603R]
R1539  0  [0402R]
R1540  33  [0402R]
R1541  10K  [0402R]
R1542  20Meg  [1206R]
R1543  0  [0603R]
R1544  10K  [0402R]
R1560  100  [0402R]
R1561  1.5K  [0402R]
R1563  100  [0402R]
R1565  10K  [0402R]
R1575  1.5K  [0402R]
R1578  0  [0402R]
SW1500  PUSH BUTTON  [SW_4P_0600x0660_VERTICAL]
U1500  ATMEGA32U4-MU  [QFN_44P_0700x0700_SLUG_0520x0520_0050CC]
U1506  FT230XQ-R  [QFN_16P_0400x0400_SLUG_0210x0210_0065CC]
U1515  TXB0102YZPR  [BGA_8P_0095x0195_0050CC_0025PD]
Y1500  16MEGHz  [XTAL_4P_0320x0250]

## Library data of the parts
11-14 = Sierra_Title_Block_0: @DATETIME: <@DATETIME>; @Name: 2500905; @SheetTotal: 15; AUTHOR: Ashish Syal; PROJECT: MANGO GREEN; REVISION_PCB: See P1; REVISION_SCH: See P1; SITE: CTO Office
C1100-C1102 C1104 C1105 C1107-C1109 C1111-C1116 C1118 C1120 C1122 C1127 C1132 C1135 C1141 C1142 C1160 C1206 C1300-C1302 C1304 C1310 C1312 C1313 C1400 C1401 C1520 C1580 = CAP_NMC0402X7R104K16TRPF: ASSEMBLY: <ASSEMBLY>; Variant Variable Text: <Variant Variable Text>
C334 C1103 C1119 C1121 C1123 = CAP_GRM155R60J475ME87D: ASSEMBLY: <ASSEMBLY>; Variant Variable Text: <Variant Variable Text>
C1106 C1124 C1214 C1500 = CAP_GRM155R61A105KE15D: ASSEMBLY: <ASSEMBLY>; Variant Variable Text: <Variant Variable Text>
C1110 C1117 C1510 C1511 = CAP_GRM1555C1H220JA01D: ASSEMBLY: <ASSEMBLY>; Variant Variable Text: <Variant Variable Text>
C1125 C1126 C1128 C1130 = CAP_GRM1555C1H150JA01D: ASSEMBLY: DNI; Variant Variable Text: DNI
C1129 C1131 C1134 C1136 = CAP_GRM155R60J475ME47D: ASSEMBLY: <ASSEMBLY>; Variant Variable Text: <Variant Variable Text>
C1133 = CAP_GRM155R71C223KA01D: ASSEMBLY: <ASSEMBLY>; Variant Variable Text: <Variant Variable Text>
C1137 = CAP_NMC0402X7R104K16TRPF: ASSEMBLY: DNI; Variant Variable Text: DNI
C1139 C1140 = CAP_GRM188R60J106ME47D: ASSEMBLY: <ASSEMBLY>; Variant Variable Text: <Variant Variable Text>
CN1100 = CN_12P_RJ45_J0011D01B: ASSEMBLY: <ASSEMBLY>; Variant Variable Text: <Variant Variable Text>
L1100 L1101 L1112 L1300 L1303 L1307 L1308 L1505 = IND_MPZ1608S221AT
OSC1100 = TCXO_4P_ABRACON: ASSEMBLY: <ASSEMBLY>; Variant Variable Text: <Variant Variable Text>
R1100-R1102 = RES_RK73B1ETTP621J: ASSEMBLY: <ASSEMBLY>; TOLERANCE: 5%; Variant Variable Text: <Variant Variable Text>
R1103 R1108 R1110-R1116 R1119 R1120 R1122 R1202 R1204 R1206 R1208-R1210 R1214 R1217 R1221 R1522 R1544 R1565 = RES_MCR01MZPF1002: ASSEMBLY: <ASSEMBLY>; TOLERANCE: 1%; Variant Variable Text: <Variant Variable Text>
R1105 R1535 = RES_RK73H1ETTP1004F: ASSEMBLY: <ASSEMBLY>; TOLERANCE: 1%; Variant Variable Text: <Variant Variable Text>
R1106 = RES_RK73H1ETTP8250F: ASSEMBLY: <ASSEMBLY>; TOLERANCE: 1%; Variant Variable Text: <Variant Variable Text>
R1107 = RES_RK73H1ETTP1242F: ASSEMBLY: <ASSEMBLY>; TOLERANCE: 1%; Variant Variable Text: <Variant Variable Text>
R1109 R1130 = RES_RK73H1ETTP1202F: ASSEMBLY: <ASSEMBLY>; TOLERANCE: 1%; Variant Variable Text: <Variant Variable Text>
R1117 R1118 R1121 R1203 R1205 R1207 R1222 R1224 = RES_MCR01MZPF1002: ASSEMBLY: DNI; TOLERANCE: 1%; Variant Variable Text: DNI
R1124-R1127 = RES_RC0805FR-7W49R9L: ASSEMBLY: <ASSEMBLY>; TOLERANCE: 1%; Variant Variable Text: <Variant Variable Text>
R1128 R1129 = RES_MCR01MZPJ331: ASSEMBLY: <ASSEMBLY>; TOLERANCE: 5%; Variant Variable Text: <Variant Variable Text>
R1131 = RES_RK73H1ETTP10R0F: ASSEMBLY: <ASSEMBLY>; TOLERANCE: 1%; Variant Variable Text: <Variant Variable Text>
R1133 = RES_UCR18EVHJSR020: ASSEMBLY: <ASSEMBLY>; TOLERANCE: 5%; Variant Variable Text: DNI
TP1100 = TESTPOINT_5P: ASSEMBLY: <ASSEMBLY>; Variant Variable Text: <Variant Variable Text>
U1100 U1104 = IC_8P_POWER_SWITCH_MIC2026: ASSEMBLY: <ASSEMBLY>; Variant Variable Text: <Variant Variable Text>
U1102 = IC_6P_MEMORY_93AA56AT: ASSEMBLY: <ASSEMBLY>; Variant Variable Text: <Variant Variable Text>
U1103 = IC_64P_LAN9514-JZX: ASSEMBLY: <ASSEMBLY>; Variant Variable Text: <Variant Variable Text>
U1105 = IC_32P_USB_HUB_USB3503: ASSEMBLY: <ASSEMBLY>; Variant Variable Text: <Variant Variable Text>
Y1100 = XTAL_4P_XRCGB25M: ASSEMBLY: <ASSEMBLY>; Variant Variable Text: <Variant Variable Text>
C1200 = CAP_TMK316ABJ106MD-T: ASSEMBLY: <ASSEMBLY>; Variant Variable Text: <Variant Variable Text>
C1202 C1203 C1215 = CAP_GCM188R71H224MA64D: ASSEMBLY: <ASSEMBLY>; Variant Variable Text: <Variant Variable Text>
C1204 = CAP_GRM155R71A473KA01D: ASSEMBLY: <ASSEMBLY>; Variant Variable Text: <Variant Variable Text>
C1205 = CAP_GRM188R61A475KE15D: ASSEMBLY: <ASSEMBLY>; Variant Variable Text: <Variant Variable Text>
C1207 = CAP_UCD1H220MCL1GS: ASSEMBLY: <ASSEMBLY>; Variant Variable Text: <Variant Variable Text>; Voltage: 50V
C1208 C1402 = CAP_GRM188R61A106ME69D: ASSEMBLY: <ASSEMBLY>; Variant Variable Text: <Variant Variable Text>
C1209 C1303 C1305 C1314-C1316 C1318 C1403 C1404 C1409 C1410 C1413 = CAP_GRM31CR61A476ME15L: ASSEMBLY: <ASSEMBLY>; Variant Variable Text: <Variant Variable Text>
C1210 = CAP_UMK107AB7105KA-T: CAP, 1uF, 50V, 10%, X7R, CERAMIC, 0603,; ASSEMBLY: <ASSEMBLY>; Variant Variable Text: <Variant Variable Text>
C1213 = CAP_GRM155R60J474KE19D: ASSEMBLY: <ASSEMBLY>; Variant Variable Text: <Variant Variable Text>
C1241 = CAP_UMK107AB7105KA-T: ASSEMBLY: <ASSEMBLY>; Variant Variable Text: DNI
CN1200 = CN_3P_DC_PWR_JACK: ASSEMBLY: <ASSEMBLY>; Variant Variable Text: <Variant Variable Text>
CN1202 = CN_2P_SINGLE_ROW_NO_BUBBLES: ASSEMBLY: <ASSEMBLY>; Variant Variable Text: <Variant Variable Text>
CN1203 = CN_2P_SINGLE_ROW: ASSEMBLY: <ASSEMBLY>; Variant Variable Text: <Variant Variable Text>
CN1204 = CN_3P_SINGLE_ROW: ASSEMBLY: <ASSEMBLY>; Variant Variable Text: <Variant Variable Text>
D1200 = DIODE_ESD_SMAJ20CA: ASSEMBLY: <ASSEMBLY>; Variant Variable Text: <Variant Variable Text>
D1201 D1210 D1500 D1501 = LED: ASSEMBLY: <ASSEMBLY>; Variant Variable Text: <Variant Variable Text>
L1200 = IND_74279252
L1201 = IND_XAL4030-332MEB
Q1200 = P_CH_MOSFET_2D_3S: ASSEMBLY: <ASSEMBLY>; Variant Variable Text: <Variant Variable Text>
Q1201 = NPN_2RES: ASSEMBLY: <ASSEMBLY>; Variant Variable Text: <Variant Variable Text>
R985 R1540 = RES_RK73B1ETTP330J: ASSEMBLY: <ASSEMBLY>; TOLERANCE: 5%; Variant Variable Text: DNI
R1211 R1285 = RES_RK73B1ETTP301J: ASSEMBLY: <ASSEMBLY>; TOLERANCE: 5%; Variant Variable Text: <Variant Variable Text>
R1212 = RES_MCR01MZPJ473: ASSEMBLY: <ASSEMBLY>; TOLERANCE: 5%; Variant Variable Text: <Variant Variable Text>
R1213 R1223 R1324 R1326 R1327 R1537 = RES_MCR03EZPJ000: ASSEMBLY: <ASSEMBLY>; TOLERANCE: 0%; Variant Variable Text: DNI
R1215 = RES_RK73H1ETTP1502F: ASSEMBLY: <ASSEMBLY>; TOLERANCE: 1%; Variant Variable Text: <Variant Variable Text>
R1216 = RES_ERJ3GEYJ104V: ASSEMBLY: <ASSEMBLY>; TOLERANCE: 5%; Variant Variable Text: <Variant Variable Text>
R1218 = RES_RK73H1ETTP1500F: ASSEMBLY: <ASSEMBLY>; TOLERANCE: 1%; Variant Variable Text: <Variant Variable Text>
R1219 = RES_MCR01MZPF3012: ASSEMBLY: <ASSEMBLY>; TOLERANCE: 1%; Variant Variable Text: <Variant Variable Text>
R1220 = RES_RK73H1ETTP5231F: ASSEMBLY: <ASSEMBLY>; TOLERANCE: 1%; Variant Variable Text: <Variant Variable Text>
R1228 R1407 R1408 R1526 R1530 R1532 = RES_RK73Z1ETTP: ASSEMBLY: <ASSEMBLY>; TOLERANCE: 0%; Variant Variable Text: DNI
R1229 R1305 R1307 = RES_RK73H1ETTP1004F: ASSEMBLY: DNI; TOLERANCE: 1%; Variant Variable Text: <Variant Variable Text>
TP1200-TP1203 TP1300-TP1305 TP1402-TP1411 = TESTPOINT: TEST POINT, ROUND, 1mm DIAMETER; CATEGORY: Layout Feature; DXDB_LIBNAME: Layout_Feature; OWNER: Michael Sorensen; Part Height: 0.01mm; REQUESTOR: Michael Sorensen
U1200 = IC_24P_BQ24192IRGER: ASSEMBLY: <ASSEMBLY>; Variant Variable Text: <Variant Variable Text>
U1201 = IC_9P_BQ27621YZFR-G1A: ASSEMBLY: <ASSEMBLY>; Variant Variable Text: <Variant Variable Text>
C1306 C1309 C1311 = CAP_GRM155R71E103KA01D: ASSEMBLY: <ASSEMBLY>; Variant Variable Text: <Variant Variable Text>
C1307 C1308 = CAP_GRM155R71E103KA01D: ASSEMBLY: <ASSEMBLY>; Variant Variable Text: DNI
C333 C1317 C1319 C1321-C1327 C1405 C1406 C1408 C1411 C1412 C1414 C1415 C1418 C1419 = CAP_GRM155R61A104KA01D: ASSEMBLY: <ASSEMBLY>; Variant Variable Text: <Variant Variable Text>
C1320 = CAP_GRM155R60G106ME44D: ASSEMBLY: <ASSEMBLY>; Variant Variable Text: <Variant Variable Text>
C350 C1330 C1420-C1426 = CAP_GRM155R61A104KA01D: ASSEMBLY: <ASSEMBLY>; Variant Variable Text: DNI
L1301 L1306 L1401-L1405 = IND_BKP1608HS121-T
L1302 L1304 = IND_FDSD0415-H-1R0M-P3
L1305 = IND_MDT2012-CH1R0N
R1302 R1303 R1318-R1323 R1336 = RES_MCR01MZPJ513: ASSEMBLY: <ASSEMBLY>; TOLERANCE: 5%; Variant Variable Text: DNI
R1306 = RES_MCR01MZPJ103: ASSEMBLY: <ASSEMBLY>; TOLERANCE: 5%; Variant Variable Text: DNI
R1308-R1311 = RES_MCR01MZPJ103: ASSEMBLY: <ASSEMBLY>; TOLERANCE: 5%; Variant Variable Text: <Variant Variable Text>
R1312 = RES_RK73Z1ETTP: ASSEMBLY: <ASSEMBLY>; TOLERANCE: 0%
R1313 = RES_RK73H1ETTP3653F: ASSEMBLY: <ASSEMBLY>; TOLERANCE: 1%; Variant Variable Text: <Variant Variable Text>
R1314 = RES_RK73H1ETTP9102F: ASSEMBLY: <ASSEMBLY>; TOLERANCE: 1%; Variant Variable Text: <Variant Variable Text>
R1315 = RES_RK73H1ETTP4993F: ASSEMBLY: <ASSEMBLY>; TOLERANCE: 1%; Variant Variable Text: <Variant Variable Text>
R1325 R1328 R1329 = RES_RK73H1ETTP1820F: ASSEMBLY: <ASSEMBLY>; TOLERANCE: 1%; Variant Variable Text: DNI
U1300 = IC_11P_TPS61230DRCR: ASSEMBLY: <ASSEMBLY>; Variant Variable Text: <Variant Variable Text>
U1301 = IC_16P_TPS62091RGTR: ASSEMBLY: <ASSEMBLY>; Variant Variable Text: <Variant Variable Text>
U1302 = IC_8P_SD_REG_SC195ULTRT: ASSEMBLY: <ASSEMBLY>; Variant Variable Text: <Variant Variable Text>
U1303-U1305 = IC_6P_LOAD_SWITCH_FPF2164: ASSEMBLY: <ASSEMBLY>; Variant Variable Text: DNI
C1407 = CAP_GRM155R71A473KA01D: ASSEMBLY: <ASSEMBLY>; Variant Variable Text: DNI
C1416 = CAP_POL-592D158X06R3R2T20H: ASSEMBLY: <ASSEMBLY>; Variant Variable Text: <Variant Variable Text>
C1417 = CAP_POL-592D158X06R3R2T20H: ASSEMBLY: <ASSEMBLY>; Variant Variable Text: DNI
Q1303 Q1304 = NPN_1: XSTR, NPN, 50V, 150mA, SOT723-3, 1.2x0.8x0.6mm; Arena Link: https://app.bom.com/a/3L4M5P8P8RAPXOE2?v=files.associations; CATEGORY: Transistor; Commodity Class: DIS - Discretes; Created Date: 2007-06-12T14:31:59-08:00; DEVICE: 5010129; DXDB_LIBNAME: Transistor; Effective Date: 2012-03-28T13:33:02-08:00; Halogen Free: N/A; Manufacturer 1: ROHM; Manufacturer 1 PN: 2SC5658T2LQ; Manufacturer 2: ON SEMICONDUCTOR; Manufacturer 2 PN: 2SC5658M3T5G; OWNER: Brian Ng; Part Height: 0.6mm; Part Status: Production; RATING: 150mA; REQUESTOR: Chris Ivanciuc; REVISION: 2; RoHS Compliant: N/A; Temperature Range: -55 +150C; VOLTAGE: 50V
R1401 R1417 = RES_RK73H1ETTP1501F: ASSEMBLY: <ASSEMBLY>; TOLERANCE: 1%; Variant Variable Text: <Variant Variable Text>
R1404 R1412 R1419 = RES_RK73H1ETTP2203F: ASSEMBLY: <ASSEMBLY>; TOLERANCE: 1%; Variant Variable Text: <Variant Variable Text>
R1405 R1421 = RES_MCR01MZPJ513: ASSEMBLY: <ASSEMBLY>; TOLERANCE: 5%; Variant Variable Text: <Variant Variable Text>
R1406 R1413 = RES_RK73H1ETTP3302F: ASSEMBLY: <ASSEMBLY>; TOLERANCE: 1%; Variant Variable Text: <Variant Variable Text>
R1414 R1416 = RES_RK73H1ETTP3302F: ASSEMBLY: <ASSEMBLY>; TOLERANCE: 1%; Variant Variable Text: DNI
R1415 = RES_POTENTIOMETER: ASSEMBLY: <ASSEMBLY>; TOLERANCE: 30%; Variant Variable Text: DNI
R1418 = RES_PF2010FRM070R1Z: ASSEMBLY: <ASSEMBLY>; TOLERANCE: 1%; Variant Variable Text: DNI
R1420 R1422 = RES_MCR01MZPF1003: ASSEMBLY: <ASSEMBLY>; TOLERANCE: 1%; Variant Variable Text: DNI
R1423 R1424 R1541 = RES_MCR01MZPF1002: ASSEMBLY: <ASSEMBLY>; TOLERANCE: 1%; Variant Variable Text: DNI
TP1400 TP1401 = TESTPOINT: TEST POINT, ROUND, 2mm DIAMETER; CATEGORY: Layout Feature; DXDB_LIBNAME: Layout_Feature; OWNER: Michael Sorensen; Part Height: 0.01mm; REQUESTOR: Michael Sorensen
U1400 = IC_20P_LDO_TPS7A7300: ASSEMBLY: <ASSEMBLY>; Variant Variable Text: <Variant Variable Text>
U1420 = IC_6P_LMP8645: ASSEMBLY: <ASSEMBLY>; Variant Variable Text: DNI
U1455 U1505 = IC_6P_LOAD_SWITCH_FPF1038: ASSEMBLY: <ASSEMBLY>; Variant Variable Text: <Variant Variable Text>
15 = Sierra_Title_Block_0: @DATETIME: <@DATETIME>; @Name: 2500905; AUTHOR: Ashish Syal; PROJECT: MANGO GREEN; REVISION_PCB: See P1; REVISION_SCH: See P1; SITE: CTO Office
C1502 C1503 C1582 C1584 = CAP_EMK105BJ105KV-F: ASSEMBLY: <ASSEMBLY>; Variant Variable Text: <Variant Variable Text>; Voltage: 16V
C1505 = CAP_GRM155R71H102KA01D: ASSEMBLY: <ASSEMBLY>; Variant Variable Text: <Variant Variable Text>
C1521 = CAP_LMK212C106MG: ASSEMBLY: <ASSEMBLY>; Variant Variable Text: <Variant Variable Text>; Voltage: 10V
CN1500 CN1503 = CN_8P_SINGLE_ROW_NO_BUBBLES: ASSEMBLY: <ASSEMBLY>; Variant Variable Text: <Variant Variable Text>
CN1501 = CN_10P_SINGLE_ROW_NO_BUBBLES: ASSEMBLY: <ASSEMBLY>; Variant Variable Text: <Variant Variable Text>
CN1502 = CN_6P_SINGLE_ROW_NO_BUBBLES: ASSEMBLY: <ASSEMBLY>; Variant Variable Text: <Variant Variable Text>
CN1504 = CN_6P_DUAL_ROW_Z_NO_BUBBLES: ASSEMBLY: <ASSEMBLY>; Variant Variable Text: <Variant Variable Text>
D401 = DIODE_ESD_SUPPRESSOR: ASSEMBLY: <ASSEMBLY>; Variant Variable Text: DNI
R1500-R1507 R1509-R1516 R1518-R1521 = RES_RK73B1ETTP330J: ASSEMBLY: <ASSEMBLY>; TOLERANCE: 5%; Variant Variable Text: <Variant Variable Text>
R1528 R1531 R1539 R1578 = RES_RK73Z1ETTP: ASSEMBLY: <ASSEMBLY>; TOLERANCE: 0%; Variant Variable Text: <Variant Variable Text>
R1538 = RES_MCR03EZPJ000: ASSEMBLY: <ASSEMBLY>; TOLERANCE: 0%; Variant Variable Text: <Variant Varibale Text>
R1542 = RES_UCR18EVHJSR020: ASSEMBLY: <ASSEMBLY>; TOLERANCE: 5%; Variant Variable Text: <Variant Variable Text>
R1543 = RES_MCR03EZPJ000: ASSEMBLY: <ASSEMBLY>; TOLERANCE: 0%; Variant Variable Text: <Variant Variable Text>
R1560 R1563 = RES_RK73B1ETTP101J: ASSEMBLY: <ASSEMBLY>; TOLERANCE: 5%; Variant Variable Text: <Variant Variable Text>
R1561 R1575 = RES_RK73B1ETTP152J: ASSEMBLY: <ASSEMBLY>; TOLERANCE: 5%; Variant Variable Text: <Variant Variable Text>
SW1500 = SW_4P_B3S-1002: ASSEMBLY: <ASSEMBLY>; Variant Variable Text: <Variant Variable Text>
U1500 = IC_44P_MC_ATMEGA32U4-MU: ASSEMBLY: <ASSEMBLY>; Variant Variable Text: <Variant Variable Text>
U1506 = IC_16P_USB_UART_FT230XQ-R: ASSEMBLY: <ASSEMBLY>; Variant Variable Text: <Variant Variable Text>
U1515 = IC_8P_TI_TXB0102YZPR: ASSEMBLY: <ASSEMBLY>; Variant Variable Text: <Variant Variable Text>
Y1500 = XTAL_4P_KX-7T-16MHZ: ASSEMBLY: <ASSEMBLY>; Variant Variable Text: <Variant Variable Text>

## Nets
GND: C333.1(A) C334.1(A) C350.1(A) C1100.1(A) C1101.1(A) C1102.1(A) C1103.1(A) C1104.1(A) C1105.1(A) C1106.2(B) C1107.1(A) C1108.1(A) C1109.1(A) C1110.1(A) C1111.1(A) C1112.1(A) C1113.1(A) C1114.1(A) C1115.1(A) C1116.1(A) C1117.1(A) C1118.1(A) C1119.1(A) C1120.1(A) C1121.1(A) C1122.1(A) C1123.1(A) C1124.2(B) C1125.1(A) C1126.1(A) C1127.1(A) C1128.1(A) C1129.1(A) C1130.1(A) C1131.1(A) C1132.1(A) C1133.1(A) C1134.1(A) C1135.1(A) C1136.1(A) C1137.1(A) C1139.1(A) C1140.1(A) C1141.1(A) C1142.1(A) C1160.1(A) C1202.1(A) C1203.1(A) C1205.1(A) C1213.1(A) C1214.2(B) C1300.1(A) C1301.1(A) C1302.1(A) C1303.1(A) C1304.1(A) C1305.1(A) C1306.1(A) C1307.1(A) C1308.1(A) C1310.1(A) C1311.1(A) C1312.1(A) C1313.1(A) C1314.1(A) C1315.1(A) C1316.1(A) C1317.1(A) C1318.1(A) C1319.1(A) C1320.1(A) C1321.1(A) C1322.1(A) C1323.1(A) C1324.1(A) C1325.1(A) C1326.1(A) C1327.1(A) C1400.1(A) C1401.1(A) C1402.1(A) C1403.1(A) C1404.1(A) C1405.1(A) C1406.1(A) C1407.1(A) C1408.1(A) C1409.1(A) C1410.1(A) C1411.1(A) C1412.1(A) C1413.1(A) C1414.1(A) C1415.1(A) C1416.2(B) C1417.2(B) C1418.1(A) C1419.1(A) C1420.1(A) C1421.1(A) C1422.1(A) C1423.1(A) C1424.1(A) C1425.1(A) C1426.1(A) C1502.1(A) C1503.1(A) C1505.1(A) C1510.1(A) C1511.1(A) C1520.1(A) C1521.1(A) C1580.1(A) C1582.1(A) C1584.1(A) CN1200.2(DET) CN1200.3(GND) CN1500.6 CN1500.7 CN1501.7 CN1504.6 D401.1 D1200.1 D1210.1(C) OSC1100.2(GND) Q1201.1(E) Q1303.E Q1304.E R1103.2(B) R1107.1(A) R1109.1(A) R1115.1(A) R1117.1(A) R1119.1(A) R1121.1(A) R1130.2(B) R1133.1(A) R1204.1(A) R1206.1(A) R1208.1(A) R1215.1(A) R1217.1(A) R1218.1(A) R1219.1(A) R1221.1(A) R1305.1(A) R1311.1(A) R1314.1(A) R1325.1(A) R1328.1(A) R1329.1(A) R1404.1(A) R1413.1(A) R1416.1(A) R1419.1(A) R1420.1(A) R1422.1(A) R1424.1(A) R1541.2(B) R1542.2(B) R1560.2(B) R1578.2(B) TP1100.5 U1100.6(GND) U1102.2(GND) U1103.34(TEST2) U1103.65(VSS_FLAG) U1104.6(GND) U1105.C3(VSS) U1200.25(PGND_3) U1201.B2(VSS_1) U1201.C1(VSS_2) U1300.11(GND) U1301.5(FB) U1301.6(AGND) U1301.14(PGND_1) U1301.15(PGND_2) U1301.17(SLUG) U1302.5(GND) U1303.5(GND1) U1303.7(GND2) U1304.5(GND1) U1304.7(GND2) U1305.5(GND1) U1305.7(GND2) U1400.8(GND_1) U1400.18(GND_2) U1400.21(GND_3) U1420.2(V-) U1455.C1(GND) U1500.15(GND_1) U1500.23(GND_2) U1500.35(GND_3) U1500.43(GND_4) U1500.45(GND_5) U1505.C1(GND) U1506.3(GND1) U1506.13(GND2) U1506.17(GND3) U1515.B1(GND) Y1100.2(GND1) Y1100.4(GND2) Y1500.2(GND1) Y1500.4(GND2) ; also on sheet 6 7 8 9 10 11 12 13 14
VBATT_BB: C1404.2(B) C1406.2(B) C1425.2(B) C1426.2(B) L1404.2(B) TP1400.1(A) ; also on sheet 14
VBATT_BB_SECONDARY: C1410.2(B) C1412.2(B) L1405.2(B) TP1403.1(A) ; also on sheet 10
VBATT_MAIN_SUPPLY: C1403.2(B) C1408.2(B) C1415.2(B) C1423.2(B) C1424.2(B) L1402.1(A) L1404.1(A) TP1402.1(A) U1455.A1(VOUT1) U1455.B1(VOUT2)
VBATT_RF: C1405.2(B) C1420.2(B) C1421.2(B) C1422.2(B) L1402.2(B) TP1401.1(A) ; also on sheet 14
VBATT_RF_SECONDARY: C1411.2(B) L1403.2(B) TP1404.1(A) ; also on sheet 10
VBATT_SECONDARY: C1409.2(B) C1418.2(B) C1419.2(B) L1403.1(A) L1405.1(A) TP1410.1(A) U1505.A1(VOUT1) U1505.B1(VOUT2)
VBUS_EXT: U1104.5(OUTB) ; also on sheet 13
VBUS_IOT0: U1100.8(OUTA) ; also on sheet 6
VBUS_IOT1: U1100.5(OUTB) ; also on sheet 6
VBUS_IOT2: U1104.8(OUTA) ; also on sheet 6
VCC_1V8: C1127.2(B) C1129.2(B) C1327.2(B) L1308.2(B) R1114.2(B) R1116.2(B) R1118.2(B) R1120.2(B) R1122.2(B) TP1305.1(A) U1105.A3(VDD_CORE_REG) U1515.C1(VCCA) U1515.C2(OE) ; also on sheet 6 7 8 9 10 11 12 13 14
VCC_1V8CORE: C1103.2(B) C1105.2(B) C1109.2(B) U1103.15(VDD18CORE) U1103.38(VDD18CORE_2)
VCC_1V8ETHPLL: C1122.2(B) C1123.2(B) L1100.2(B) U1103.48(VDD18ETHPLL)
VCC_1V8USBPLL: C1119.2(B) L1100.1(A) U1103.62(VDD18USBPLL)
VCC_3V3: C1100.2(B) C1101.2(B) C1108.2(B) C1131.2(B) C1132.2(B) C1137.2(B) C1139.2(B) C1141.2(B) C1326.2(B) CN1100.9(LED1_A) CN1100.12(LED2_A) CN1500.4 L1101.1(A) L1112.1(A) L1307.2(B) OSC1100.1(OE) OSC1100.4(VCC) R1106.1(A) R1108.2(B) R1110.2(B) R1111.2(B) R1112.2(B) R1113.2(B) R1303.2(B) R1336.1(A) R1530.1(A) R1537.1(A) TP1303.1(A) U1102.6(VCC) U1103.40(TEST3) U1105.B2(VBAT) ; also on sheet 6 7 8 11 12 13
VCC_3V3AA: C1102.2(B) C1104.2(B) C1107.2(B) C1112.2(B) C1114.2(B) C1116.2(B) C1121.2(B) C1142.2(B) L1101.2(B) R1124.2(B) R1125.2(B) R1126.2(B) R1127.2(B) R1131.2(B) U1103.5(VDD33A) U1103.10(VDD33A_2) U1103.49(VDD33A_3) U1103.51(VDD33A_4) U1103.54(VDD33A_5) U1103.57(VDD33A_6) U1103.64(VDD33A_7)
VCC_3V7: C1300.2(B) C1301.2(B) C1310.2(B) C1400.2(B) L1300.1(A) L1301.1(A) L1303.1(A) L1401.1(A) R1223.2(B) R1285.2(B) TP1201.1(A) ; also on sheet 8 9 10 11 12 14
VCC_5V0: C1106.1(A) C1124.1(A) C1325.2(B) C1521.2(B) CN1500.5 L1306.2(B) R1531.1(A) R1538.1(A) TP1301.1(A) U1100.7(IN) U1104.7(IN) U1500.7(VBUS) ; also on sheet 13
VCC_ARD: C1502.2(B) C1503.2(B) C1582.2(B) C1584.2(B) CN1500.2 CN1500.8 CN1504.2 D1500.2(A) D1501.2(A) L1505.2(B) R1522.1(A) R1526.1(A) R1528.1(A) R1537.2(B) R1538.2(B) R1565.1(A) U1500.14(VCC_1) U1500.34(VCC_2) U1515.B2(VCCB) ; also on sheet 10
VCC_CF3_FILT: C1413.2(B) C1414.2(B) C1416.1(A) C1417.1(A) R1401.2(B) R1405.2(B) R1407.2(B) R1408.2(B) R1412.2(B) R1414.2(B) R1417.2(B) R1421.2(B) TP1407.1(A) U1400.1(OUT) U1400.19(OUT_2) U1400.20(OUT_3) U1455.A2(VIN1) U1455.B2(VIN2) U1505.A2(VIN1) U1505.B2(VIN2)
VDD_3V3BYP: C1136.2(B) U1105.A2(VDD33_BYP) U1105.A5(VDD33_BYP_2)
$10I34853: U1103.31(TDO)
$10I34855: U1103.13(TEST1)
$10I34856: U1103.47(TEST4)
$10I34857: U1103.43(GPIO7)
$10I34858: U1103.42(GPIO6)
$10I34859: U1103.36(GPIO4)
$10I34860: U1103.37(GPIO5)
$10I34861: U1103.35(GPIO3)
$10I34862: U1103.20(nFDX_LED/GPPIO0)
$10I36502: U1105.C4(PORT_PWR)
$10I37561: CN1100.7(NC)
$10I40185: U1103.45(CLK24_OUT)
$16I30035: CN1500.1
$16I31654: U1506.14(CBUS3)
$16I31656: U1506.5(CBUS2)
$16I31658: U1506.11(CBUS1)
$16I31660: U1506.12(CBUS0)
$16I31662: U1506.4(CTS_N)
$16I31664: U1506.16(RTS_N)
$18I35378: U1400.5(50mV)
$18I35380: U1400.6(100mV)
$18I35382: U1400.7(200mV)
$18I35384: U1400.9(400mV)
$18I35386: U1400.10(800mV)
$18I35388: U1400.11(1.6V)
$18I35390: U1400.12(NC)
A0: CN1502.1 U1500.36(PF7)
A1: CN1502.2 U1500.37(PF6)
A2: CN1502.3 U1500.38(PF5)
A3: CN1502.4 U1500.39(PF4)
A4: CN1502.5 U1500.40(PF1)
A5: CN1502.6 U1500.41(PF0)
ARD_FTDI: R1543.1(A) ; also on sheet 7
ARDUINO_RESET: C1520.2(B) CN1500.3 D401.2 R1520.1(A) R1522.2(B) R1540.1(A) R1563.2(B) SW1500.3(B1) SW1500.4(B2)
ARDUINO_RESET_Level shift: U1515.D2(A1) ; also on sheet 7
AREF: C1505.2(B) C1580.2(B) CN1501.8 U1500.42(AREF)
BATTCHRGR_INT_N: R1202.1(A) U1200.7(INT) ; also on sheet 7
BATTCHRGR_PG_N: R1210.1(A) U1200.3(PG_N) ; also on sheet 7
BATTERY_DETECT: R985.2(B) ; also on sheet 7 14
BATTGAUGE_GPIO: R1224.1(A) U1201.A1(GPOUT) ; also on sheet 7
CHARGER_I2C_CLK: U1200.5(SCL) ; also on sheet 9
CHARGER_I2C_DATA: U1200.6(SDA) ; also on sheet 9
CORRECT_INSERTION: Q1303.B R1401.1(A) R1404.2(B) ; also on sheet 14
D0/RX: R1509.2(B) U1500.20(PD2) U1506.15(TXD) ; also on sheet 10
D1/TX: R1510.2(B) U1500.21(PD3) U1506.2(RXD) ; also on sheet 10
D2/SDA: R1506.2(B) R1511.2(B) U1500.19(PD1)
D3/SCL: R1507.2(B) R1512.2(B) U1500.18(PD0)
D4: R1513.2(B) U1500.25(PD4)
D5: R1514.2(B) U1500.31(PC6)
D6: R1515.2(B) U1500.27(PD7)
D7: R1516.2(B) U1500.1(PE6)
DCDC_SHUTDOWN: C1307.2(B) R1302.2(B) U1301.13(EN) ; also on sheet 12
EECLK: R1102.1(A) U1103.23(EECLK)
EECS: R1101.1(A) U1103.24(EECS)
EEDI: TP1100.4 U1102.1(DO) U1103.26(EEDI)
EEDO: R1100.1(A) U1103.25(EEDO)
EN_LDO: R1406.1(A) U1400.14(EN)
ENA_1V8: C1313.2(B) R1306.1(A) R1308.1(A) R1309.1(A) R1310.1(A) R1336.2(B)
ENA_5V: C1308.2(B) R1303.1(A) U1300.9(EN)
ETH_GND: CN1100.8(GND_1) CN1100.13(GND_2) CN1100.14(GND_3) R1133.2(B)
GPIO1/I2C1_CLK: U1201.A3(SCL) ; also on sheet 9 10 11 14
GPIO5/I2C1_DATA: U1201.A2(SDA) ; also on sheet 9 10 11 14
HSIC_DATA: U1105.E2(DATA) ; also on sheet 14
HSIC_STRB: U1105.E1(STROBE) ; also on sheet 14
HUB_CONNECT: R1120.1(A) R1121.2(B) U1105.B5(HUB_CONNECT) ; also on sheet 7
HUB_I2C_CLK: U1105.E5(SCL) ; also on sheet 9
HUB_I2C_DATA: U1105.D5(SDA) ; also on sheet 9
IO8: R1500.2(B) U1500.28(PB4)
IO9: R1501.2(B) U1500.29(PB5)
IO10: R1502.2(B) U1500.30(PB6)
IO11: R1503.2(B) U1500.12(PB7)
IO12: R1504.2(B) U1500.26(PD6)
IO13: R1505.2(B) U1500.32(PC7)
LDO_PG: U1400.4(PG) ; also on sheet 12
MISO: R1518.1(A) U1500.11(PB3)
MOSI: R1521.2(B) U1500.10(PB2)
NLNKA_LED_GPIO1: R1128.1(A) U1103.21(nLNKA_LED/GPIO1)
NSPDA_LED_GPIO2: R1129.1(A) U1103.22(nSPD_LED/GPIO2)
PG_3V3: R1315.1(A) U1301.4(PG)
PMID: C1200.2(B) C1241.2(B) U1200.23(PMID)
PRTCTL2: U1100.1(ENA) U1100.2(FLGA) U1103.14(PRTCTL2)
PRTCTL3: U1100.3(FLGB) U1100.4(ENB) U1103.16(PRTCLT3)
PRTCTL4: U1103.17(PRTCLTL4) U1104.1(ENA) U1104.2(FLGA)
PRTCTL5: U1103.18(PRTCTL5) U1104.3(FLGB) U1104.4(ENB)
PWR_GND_BQ: C1200.1(A) C1206.1(A) C1207.2(B) C1208.1(A) C1209.1(A) C1210.1(A) C1215.1(A) C1241.1(A) CN1202.2 U1200.17(PGND_1) U1200.18(PGND_2)
REGN_BATT: C1205.2(B) R1207.2(B) R1214.2(B) R1220.2(B) U1200.22(REGN)
RXLED/SS: R1561.1(A) U1500.8(PB0)
RXN: C1130.2(B) CN1100.6(RD-) R1127.1(A) U1103.53(RXN)
RXP: C1128.2(B) CN1100.3(RD+) R1126.1(A) U1103.52(RXP)
S_CORRECT_INSERTION: Q1304.B R1417.1(A) R1419.2(B) ; also on sheet 10
SCK: R1519.1(A) U1500.9(PB1)
STAT_BATT: D1201.1(C) R1212.1(A) U1200.4(STAT)
SYSTEM_RESET: U1105.E3(RESET_N) ; also on sheet 7 9 12
SYSTEM_RESET_3V3: U1103.12(NRESET) ; also on sheet 12
TEMP_SENS: CN1203.2 R1219.2(B) R1220.1(A) R1222.2(B) R1228.1(A) TP1203.1(A) U1200.11(TS1)
TXLED: R1575.1(A) U1500.22(PD5)
TXN: C1126.2(B) CN1100.2(TD-) R1125.1(A) U1103.56(TXN)
TXP: C1125.2(B) CN1100.1(TD+) R1124.1(A) U1103.55(TXP)
UGND: C1500.1(A) R1542.1(A) U1500.5(UGND)
USB1_D+: U1105.A1(USBDN1_DP) U1506.6(USBDP)
USB1_D-: U1105.B1(USBDN1_DM) U1506.7(USBDM)
USB2_D+: U1105.C2(USBDN2_DP) ; also on sheet 10
USB2_D-: U1105.D2(USBDN2_DM) ; also on sheet 10
USB3_D+: U1103.59(USBDP0) U1105.C1(USBDN3_DP)
USB3_D-: U1103.58(USBDM0) U1105.D1(USBDN3_DM)
USB4_D+: U1103.9(USBDP5) ; also on sheet 6
USB4_D-: U1103.8(USBDM5) ; also on sheet 6
USB5_D+: U1103.7(USBDP4) ; also on sheet 6
USB5_D-: U1103.6(USBDM4) ; also on sheet 6
USB6_D+: U1103.4(USBDP3) ; also on sheet 6
USB6_D-: U1103.3(USBDM3) ; also on sheet 6
USB7_D+: U1103.2(USBDP2) ; also on sheet 13
USB7_D-: U1103.1(USBDM2) ; also on sheet 13
USB_HUB_INTN: R1114.1(A) U1105.C5(INT_N) ; also on sheet 7
USB_VBUS: CN1204.1 ; also on sheet 13
USBD+_ARD: U1500.4(D+) ; also on sheet 13
USBD-_ARD: U1500.3(D-) ; also on sheet 13
V_BATT: C1208.2(B) C1214.1(A) CN1202.1 Q1201.2(B) TP1202.1(A) U1200.13(BAT_1) U1200.14(BAT_2) U1201.C2(BAT_1) U1201.C3(BAT_2)
V_IN: C1207.1(A) C1210.2(B) C1215.2(B) Q1200.A2(S) Q1200.B1(S2) Q1200.B2(S3) R1213.2(B) R1216.2(B) TP1200.1(A) U1200.1(VBUS) U1200.24(VBUS_2)
V_SYS_BATT: C1206.2(B) C1209.2(B) L1201.2(B) R1202.2(B) R1203.2(B) R1205.2(B) R1210.2(B) R1211.1(A) R1212.2(B) R1223.1(A) U1200.15(SYS_1) U1200.16(SYS_2)
VGPIO: R1209.2(B) R1224.2(B) ; also on sheet 6 12 13 14
WP2ARDUINO_RESET: U1515.D1(A2) ; also on sheet 12
WP2ARDUINO_RESET_LEVEL: R1563.1(A) R1565.2(B) U1500.13(RESET_N) U1515.A1(B2)
XTAL1: C1510.2(B) R1535.1(A) U1500.17(XTAL1) Y1500.1
XTAL2: C1511.2(B) R1535.2(B) U1500.16(XTAL2) Y1500.3
$10N32328: C1111.2(B) C1113.2(B) C1115.2(B) C1118.2(B) C1120.2(B) C1140.2(B) C1160.2(B) L1112.2(B) U1103.19(VDD33IO) U1103.27(VDD33IO_2) U1103.33(VDD33IO_3) U1103.39(VDD33IO_4) U1103.46(VDD33IO_5)
$10N32341: R1109.2(B) U1103.63(USBRBIAS)
$10N32347: R1107.2(B) U1103.50(EXRES)
$10N32348: R1110.1(A) U1103.41(AUTOMDIX_EN)
$10N32539: C1110.2(B) R1105.2(B) U1103.61(XI) Y1100.1
$10N32541: C1117.2(B) R1105.1(A) U1103.60(XO) Y1100.3
$10N32581: R1108.1(A) U1103.28(NTRST)
$10N33520: R1130.1(A) U1105.A4(RBIAS)
$10N33600: C1134.2(B) C1135.2(B) U1105.D3(VDD12_BYP)
$10N33642: R1118.1(A) R1119.2(B) U1105.D4(REF_SEL1)
$10N33643: R1116.1(A) R1117.2(B) U1105.E4(REF_SEL0)
$10N33924: R1122.1(A) U1105.B4(OCS_N)
$10N34065: OSC1100.3(OUT) U1105.B3(REFCLK)
$10N35950: CN1100.11(LED2_C) R1129.2(B)
$10N35951: CN1100.10(LED1_C) R1128.2(B)
$10N36447: R1106.2(B) U1103.11(VBUS_DET)
$10N36797: R1115.2(B) U1103.44(CLK24_EN)
$10N37557: C1133.2(B) CN1100.4(TD_CT) CN1100.5(RD_CT) R1131.1(A)
$10N37808: R1113.1(A) U1103.32(TCK)
$10N37810: R1112.1(A) U1103.30(TDI)
$10N37812: R1111.1(A) U1103.29(TMS)
$10N40400: R1102.2(B) TP1100.3 U1102.4(CLK)
$10N40402: R1100.2(B) TP1100.1 U1102.3(DI)
$10N40404: R1101.2(B) R1103.1(A) TP1100.2 U1102.5(CS)
$14N2464: R1207.1(A) R1208.2(B) U1200.2(PSEL)
$14N2465: D1201.2(A) R1211.2(B)
$14N2471: R1203.1(A) R1204.2(B) U1200.8(OTG)
$14N2478: Q1200.A1(G) R1216.1(A) R1217.2(B)
$14N2479: C1203.2(B) D1200.2 L1200.2(B) Q1200.C1(D) Q1200.C2(D2) R1213.1(A)
$14N2480: C1202.2(B) CN1204.2 L1200.1(A)
$14N5952: CN1203.1 R1221.2(B) R1228.2(B)
$14N6138: C1213.2(B) R1229.1(A) U1201.B3(VDD)
$14N6187: R1222.1(A) R1229.2(B) U1201.B1(BIN)
$14N7072: D1210.2(A) R1285.1(A)
$14N7692: CN1200.1(VCC) CN1204.3
$14N8447: Q1201.6(C) R985.1(A) R1209.1(A)
$16N26756: L1505.1(A) U1500.24(AVCC_1) U1500.44(AVCC_2)
$16N27394: R1528.2(B) U1500.2(UVCC)
$16N27395: C1500.2(B) R1526.2(B) U1500.6(UCAP)
$16N28693: D1501.1(C) R1561.2(B)
$16N28855: R1578.1(A) U1500.33(PE2)
$16N29167: R1560.1(A) SW1500.1(A1) SW1500.2(A2)
$16N29942: CN1501.2 R1501.1(A)
$16N29943: CN1501.1 R1500.1(A)
$16N29965: CN1503.1 R1509.1(A)
$16N29966: CN1503.2 R1510.1(A)
$16N29967: CN1503.4 R1512.1(A)
$16N29968: CN1503.3 R1511.1(A)
$16N29969: CN1503.5 R1513.1(A)
$16N29970: CN1503.6 R1514.1(A)
$16N29971: CN1503.7 R1515.1(A)
$16N29972: CN1503.8 R1516.1(A)
$16N29973: CN1501.10 R1507.1(A)
$16N29974: CN1501.9 R1506.1(A)
$16N29975: CN1501.6 R1505.1(A)
$16N29976: CN1501.5 R1504.1(A)
$16N29977: CN1501.4 R1503.1(A)
$16N29978: CN1501.3 R1502.1(A)
$16N29979: CN1504.1 R1518.2(B)
$16N29980: CN1504.3 R1519.2(B)
$16N29981: CN1504.5 R1520.2(B)
$16N29982: CN1504.4 R1521.1(A)
$16N31435: R1541.1(A) R1543.2(B) R1544.2(B) U1506.9(RESET_N)
$16N31436: C350.2(B) R1530.2(B) R1532.1(A) R1539.1(A) R1544.1(A) U1506.1(VCCIO)
$16N31596: R1539.2(B) U1506.8(3V3OUT)
$16N32121: C333.2(B) C334.2(B) R1531.2(B) R1532.2(B) U1506.10(VCC)
$17N147: C1315.2(B) C1316.2(B) C1317.2(B) C1330.2(B) R1307.2(B) R1313.2(B) R1318.1(A) R1319.1(A) R1324.1(A) TP1300.1(A) U1300.3(VOUT_1) U1300.4(VOUT_2) U1303.2(VIN)
$17N212: C1304.2(B) C1305.2(B) L1301.2(B) L1302.1(A) U1300.10(VIN)
$17N344: C1306.2(B) U1300.6(SS)
$17N481: C1312.2(B) C1314.2(B) L1303.2(B) R1306.2(B) U1302.7(IN)
$17N640: R1308.2(B) U1302.3(CTL0)
$17N672: R1309.2(B) U1302.2(CTL1)
$17N704: R1310.2(B) U1302.1(CTL2)
$17N736: R1311.2(B) U1302.8(CTL3)
$17N1057: L1305.1(A) U1302.6(LX)
$17N1058: C1320.2(B) C1322.2(B) L1305.2(B) R1322.1(A) R1323.1(A) R1327.1(A) TP1304.1(A) U1302.4(OUT) U1305.2(VIN)
$17N1540: C1318.2(B) C1319.2(B) L1304.2(B) R1315.2(B) R1320.1(A) R1321.1(A) R1326.1(A) TP1302.1(A) U1301.16(VOS) U1304.2(VIN)
$17N1703: C1309.2(B) U1301.8(CN)
$17N1705: C1309.1(A) U1301.7(CP)
$17N1740: C1311.2(B) U1301.9(SS)
$17N1885: C1302.2(B) C1303.2(B) L1300.2(B) R1302.1(A) R1312.1(A) U1301.10(AVIN) U1301.11(PVIN_2) U1301.12(PVIN_1)
$17N2275: C1330.1(A) R1313.1(A) R1314.2(B) U1300.7(FB)
$17N2315: R1307.1(A) U1300.5(PG)
$17N2349: R1305.2(B) U1300.8(HSY)
$17N3093: C1321.2(B) L1306.1(A) R1324.2(B) U1303.3(VOUT)
$17N3237: R1318.2(B) U1303.4(FLAGB)
$17N3240: R1319.2(B) U1303.6(ON)
$17N3314: R1325.2(B) U1303.1(ISET)
$17N3322: R1320.2(B) U1304.4(FLAGB)
$17N3323: R1321.2(B) U1304.6(ON)
$17N3334: R1328.2(B) U1304.1(ISET)
$17N3574: R1322.2(B) U1305.4(FLAGB)
$17N3575: R1323.2(B) U1305.6(ON)
$17N3584: C1324.2(B) L1308.1(A) R1327.2(B) U1305.3(VOUT)
$18N32578: C1401.2(B) C1402.2(B) L1401.2(B) R1406.2(B) R1407.1(A) U1400.15(IN_1) U1400.16(IN_2) U1400.17(IN_3)
$18N33265: R1412.1(A) R1413.2(B) R1415.2(TRIM) U1400.3(FB)
$18N33327: C1407.2(B) U1400.13(SS)
$18N33364: R1408.1(A) U1400.2(SNS)
$18N33931: R1414.1(A) R1415.3(CW)
$18N33964: R1415.1(CCW) R1416.2(B)
$18N34003: Q1303.C R1405.1(A) U1455.C2(ON)
$18N34685: Q1304.C R1421.1(A) U1505.C2(ON)
$18N35450: R1418.2(B) TP1406.1(A) U1420.3(+IN)
$18N35452: R1418.1(A) TP1405.1(A) U1420.4(-IN)
$18N35519: R1420.2(B) R1422.2(B) U1420.5(RG)
$18N35526: TP1408.1(A) U1420.6(V+)
$18N35665: R1423.1(A) TP1409.1(A) U1420.1(VOUT)
$18N35667: R1423.2(B) R1424.2(B) TP1411.1(A)
N1677546: C1204.2(B) L1201.1(A) U1200.19(SW_1) U1200.20(SW_2)
N1677578: R1205.1(A) R1206.2(B) U1200.9(CE_N)
N1680386: R1218.2(B) U1200.10(ILIM)
N1680390: R1214.1(A) R1215.2(B) U1200.12(TS2)
N1680804: C1204.1(A) U1200.21(BTST)
N1684388: L1304.1(A) U1301.1(SW) U1301.2(SW)
N1684400: R1312.2(B) U1301.3(FREQ)
N1684420: C1323.2(B) L1307.1(A) R1326.2(B) U1304.3(VOUT)
N1684568: R1329.2(B) U1305.1(ISET)
N1685348: L1302.2(B) U1300.1(SW) U1300.2(SW)
N1698276: R1540.2(B) U1515.A2(B1)
N1701788: D1500.1(C) R1575.2(B)

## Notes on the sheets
sheet 1
- Make sure to line up Arduino connector orientation properly
- Arduino Connector
- ARDUINO_RESET: Need to connect: use level shifter
- IOH
- Power
- ADC
- IOL
- Self powered mode
- ICSP
- If powered by 5V populate R1531 and R1539
- If powered by 3.3V populate R1530, R1532, R1539 and C350
- If VCC=5V and VCCIO = 3.3V populate R1530, R1531, R1539 and C350 - (remove R1532)
- ARDUINO Voltage Select
- Default to 5V
- Arduino RESET
- Match reset to how it is done on Leonardo
sheet 2
- CF3 LDO
- Vout = 3.8V
- Bigger Size
- Bigger Size
sheet 3
- 5V boost, 3V3 and 1V8 Buck
- Current Limit = 1.5A typ
- Replace with FPF2163 if Autorestart is required
- Current Limit = 1.5A typ
- Replace with FPF2163 if Autorestart is required
- Current Limit = 1.5A typ
- Replace with FPF2163 if Autorestart is required
sheet 4
- PSU Front End and 3.7V DC/DC converter
- MAX OPERATIVE INPUT VOLTAGE  = 17V
- MIN OPERATIVE INPUT VOLTAGE  = 5V (3.9V with BATT)
- (ABSOLUTE MAX INPUT VOLTAGE = 20V)
- Imax= 3.8A
- Notes:
- * For High Reliability systems use the
- WD feature of BQ24292i
- * Voltage on ILIM can be
- measured to monitor total
- input current on device
- Default value 2.2uH
- V > 20V
- Place as close as possible
- I2C address 1010101b
- I2C address 1010101b
- I2C address 6BH
- I2C address 55H
- I_lim_max = 3.5A
- Ideal battery should have a 103-AT thermistor inside
- If using battery with no thermistor then short Pin1 and Pin2 of CN1203
- PCB layout note
- Connect PWR_GND_BQ and Main ground
- together using Pin 25 as connection point
sheet 5
- LAN9514
- ETHERNET JACK
- Place 49.9R near LAN9514
- Place 10R near transformer
- TP for IN Circuit Programming
- This could be a zero ohm, a cap or and inductor
- USB 3503
- Power Filter
- I2C address: 00001000b
- I2C address: 08h
- USB Downstream Power
